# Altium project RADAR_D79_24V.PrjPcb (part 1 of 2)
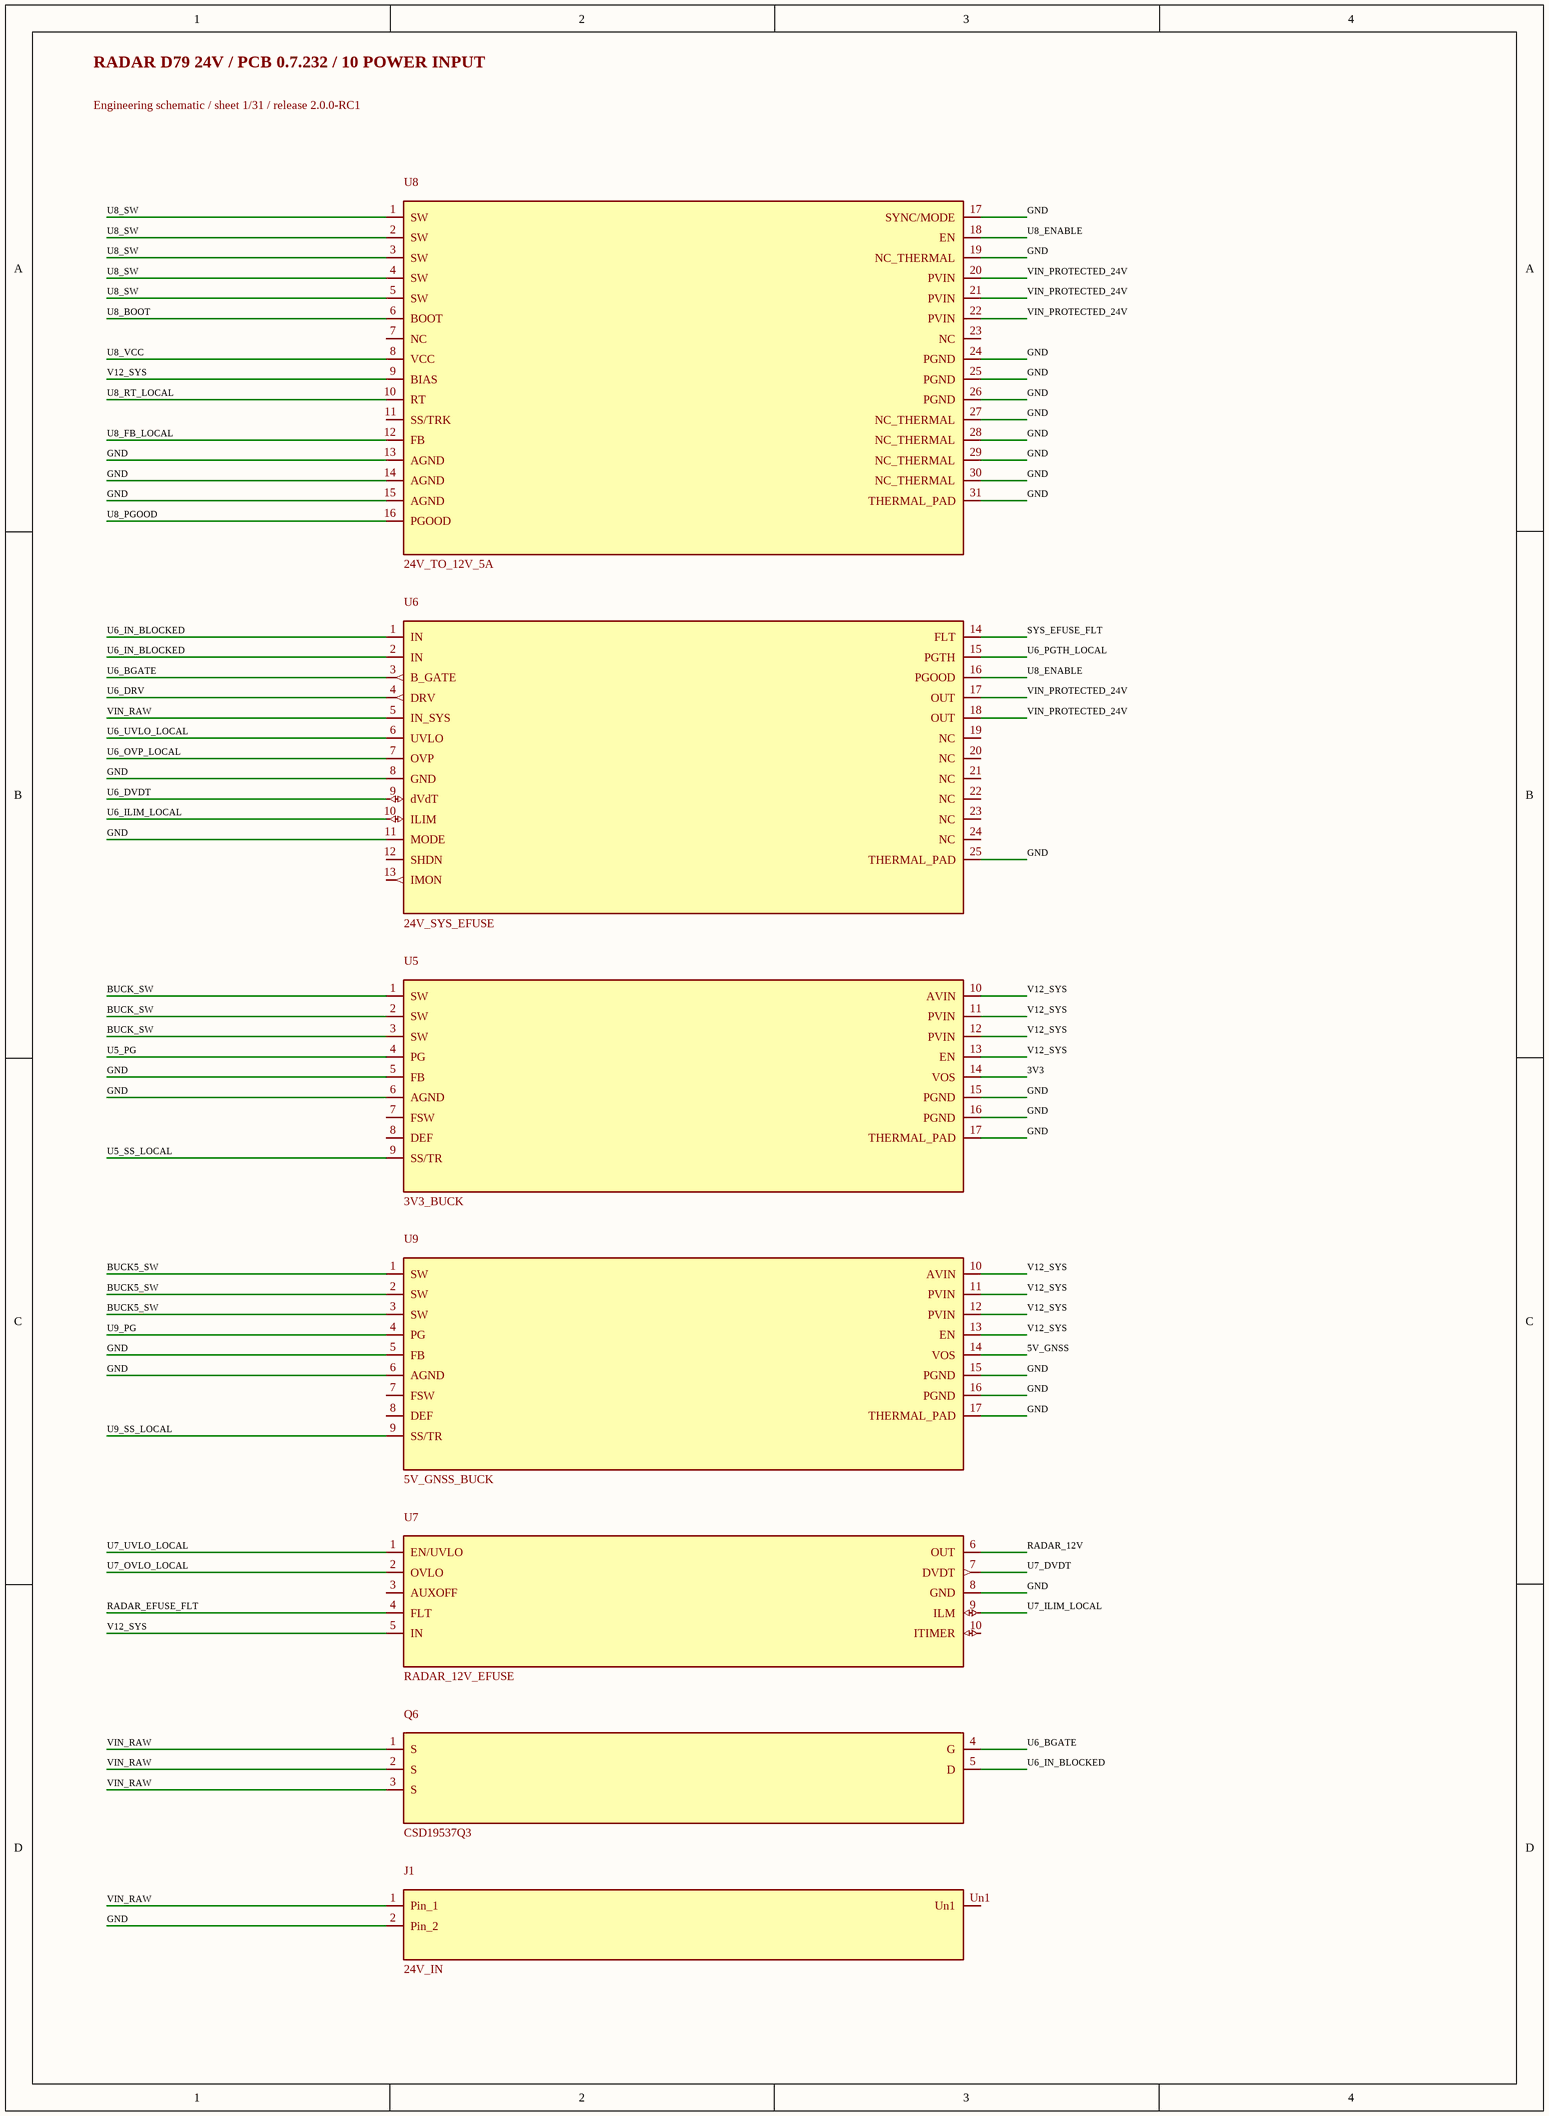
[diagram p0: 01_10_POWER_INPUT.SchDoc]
31 sheets, 304 parts. Net scope: global (net labels, ports and power ports of the same name join across sheets).
Board file: RADAR_D79_POWER_24V_v0.7.232.PcbDoc
Sheets:
  01_10_POWER_INPUT.SchDoc
  02_10_POWER_INPUT.SchDoc
  03_10_POWER_INPUT.SchDoc
  04_10_POWER_INPUT.SchDoc
  05_60_HOST_UART.SchDoc
  06_50_RADAR_IO_CAN.SchDoc
  07_70_DEBUG_BOOT.SchDoc
  08_30_TIME_GNSS.SchDoc
  09_20_MCU_CORE.SchDoc
  10_20_MCU_CORE.SchDoc
  11_20_MCU_CORE.SchDoc
  12_40_IMU.SchDoc
  13_Radar_interfaces_and_QSPI.SchDoc
  14_Radar_interfaces_and_QSPI.SchDoc
  15_Radar_interfaces_and_QSPI.SchDoc
  16_Radar_service_USB_and_boot.SchDoc
  17_Radar_service_USB_and_boot.SchDoc
  18_Radar_service_USB_and_boot.SchDoc
  19_Radar_12V_to_3V3.SchDoc
  20_Radar_12V_to_3V3.SchDoc
  21_Radar_input_and_reference.SchDoc
  22_Radar_bypass.SchDoc
  23_Radar_bypass.SchDoc
  24_Radar_bypass.SchDoc
  25_Radar_PMIC_and_rail_filters.SchDoc
  26_Radar_PMIC_and_rail_filters.SchDoc
  27_Radar_PMIC_and_rail_filters.SchDoc
  28_Radar_PMIC_and_rail_filters.SchDoc
  29_Radar_rail_selection_and_sensing.SchDoc
  30_Radar_rail_selection_and_sensing.SchDoc
  31_Radar_VPP_service.SchDoc

## Sheet 01_10_POWER_INPUT.SchDoc
size 289 x 396 mm

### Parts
J1  24V_IN  [Molex_43650-0200_RA_THT_2P]
Q6  CSD19537Q3  [VSON-8_3.3x3.3mm_P0.65mm_NexFET]
U5  3V3_BUCK  [VQFN-16-1EP_3x3mm_P0.5mm_EP1.68x1.68mm]
U6  24V_SYS_EFUSE  [Texas_RGE0024C_VQFN-24-1EP_4x4mm_P0.5mm_EP2.1x2.1mm]
U7  RADAR_12V_EFUSE  [TPS259470A_RPW0010A_VQFN-HR-10_2x2mm_P0.475mm]
U8  24V_TO_12V_5A  [Texas_RNP0030B_WQFN-30-1EP_4x6mm_P0.5mm_EP1.8x4.5mm_ThermalVias]
U9  5V_GNSS_BUCK  [VQFN-16-1EP_3x3mm_P0.5mm_EP1.68x1.68mm]

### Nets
3V3: U5.14(VOS)
5V_GNSS: U9.14(VOS)
BUCK5_SW: U9.1(SW) U9.2(SW) U9.3(SW)
BUCK_SW: U5.1(SW) U5.2(SW) U5.3(SW)
GND: J1.2(Pin_2) U5.5(FB) U5.6(AGND) U5.15(PGND) U5.16(PGND) U5.17(THERMAL_PAD) U6.8(GND) U6.11(MODE) U6.25(THERMAL_PAD) U7.8(GND) U8.13(AGND) U8.14(AGND) U8.15(AGND) U8.17(SYNC/MODE) U8.19(NC_THERMAL) U8.24(PGND) U8.25(PGND) U8.26(PGND) U8.27(NC_THERMAL) U8.28(NC_THERMAL) U8.29(NC_THERMAL) U8.30(NC_THERMAL) U8.31(THERMAL_PAD) U9.5(FB) U9.6(AGND) U9.15(PGND) U9.16(PGND) U9.17(THERMAL_PAD)
RADAR_12V: U7.6(OUT)
RADAR_EFUSE_FLT: U7.4(FLT)
SYS_EFUSE_FLT: U6.14(FLT)
U5_PG: U5.4(PG)
U5_SS_LOCAL: U5.9(SS/TR)
U6_BGATE: Q6.4(G) U6.3(B_GATE)
U6_DRV: U6.4(DRV)
U6_DVDT: U6.9(dVdT)
U6_ILIM_LOCAL: U6.10(ILIM)
U6_IN_BLOCKED: Q6.5(D) U6.1(IN) U6.2(IN)
U6_OVP_LOCAL: U6.7(OVP)
U6_PGTH_LOCAL: U6.15(PGTH)
U6_UVLO_LOCAL: U6.6(UVLO)
U7_DVDT: U7.7(DVDT)
U7_ILIM_LOCAL: U7.9(ILM)
U7_OVLO_LOCAL: U7.2(OVLO)
U7_UVLO_LOCAL: U7.1(EN/UVLO)
U8_BOOT: U8.6(BOOT)
U8_ENABLE: U6.16(PGOOD) U8.18(EN)
U8_FB_LOCAL: U8.12(FB)
U8_PGOOD: U8.16(PGOOD)
U8_RT_LOCAL: U8.10(RT)
U8_SW: U8.1(SW) U8.2(SW) U8.3(SW) U8.4(SW) U8.5(SW)
U8_VCC: U8.8(VCC)
U9_PG: U9.4(PG)
U9_SS_LOCAL: U9.9(SS/TR)
V12_SYS: U5.10(AVIN) U5.11(PVIN) U5.12(PVIN) U5.13(EN) U7.5(IN) U8.9(BIAS) U9.10(AVIN) U9.11(PVIN) U9.12(PVIN) U9.13(EN)
VIN_PROTECTED_24V: U6.17(OUT) U6.18(OUT) U8.20(PVIN) U8.21(PVIN) U8.22(PVIN)
VIN_RAW: J1.1(Pin_1) Q6.1(S) Q6.2(S) Q6.3(S) U6.5(IN_SYS)

Not connected (* = marked no-connect by the designer): J1 Un1; U5 7(FSW) 8(DEF); U6 12(SHDN) 13(IMON) 19(NC) 20(NC) 21(NC) 22(NC) 23(NC) 24(NC); U7 3(AUXOFF) 10(ITIMER); U8 7(NC) 11(SS/TRK) 23(NC); U9 7(FSW) 8(DEF)

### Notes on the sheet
- RADAR D79 24V / PCB 0.7.232 / 10 POWER INPUT
- Engineering schematic / sheet 1/31 / release 2.0.0-RC1

## Sheet 02_10_POWER_INPUT.SchDoc
size 289 x 396 mm
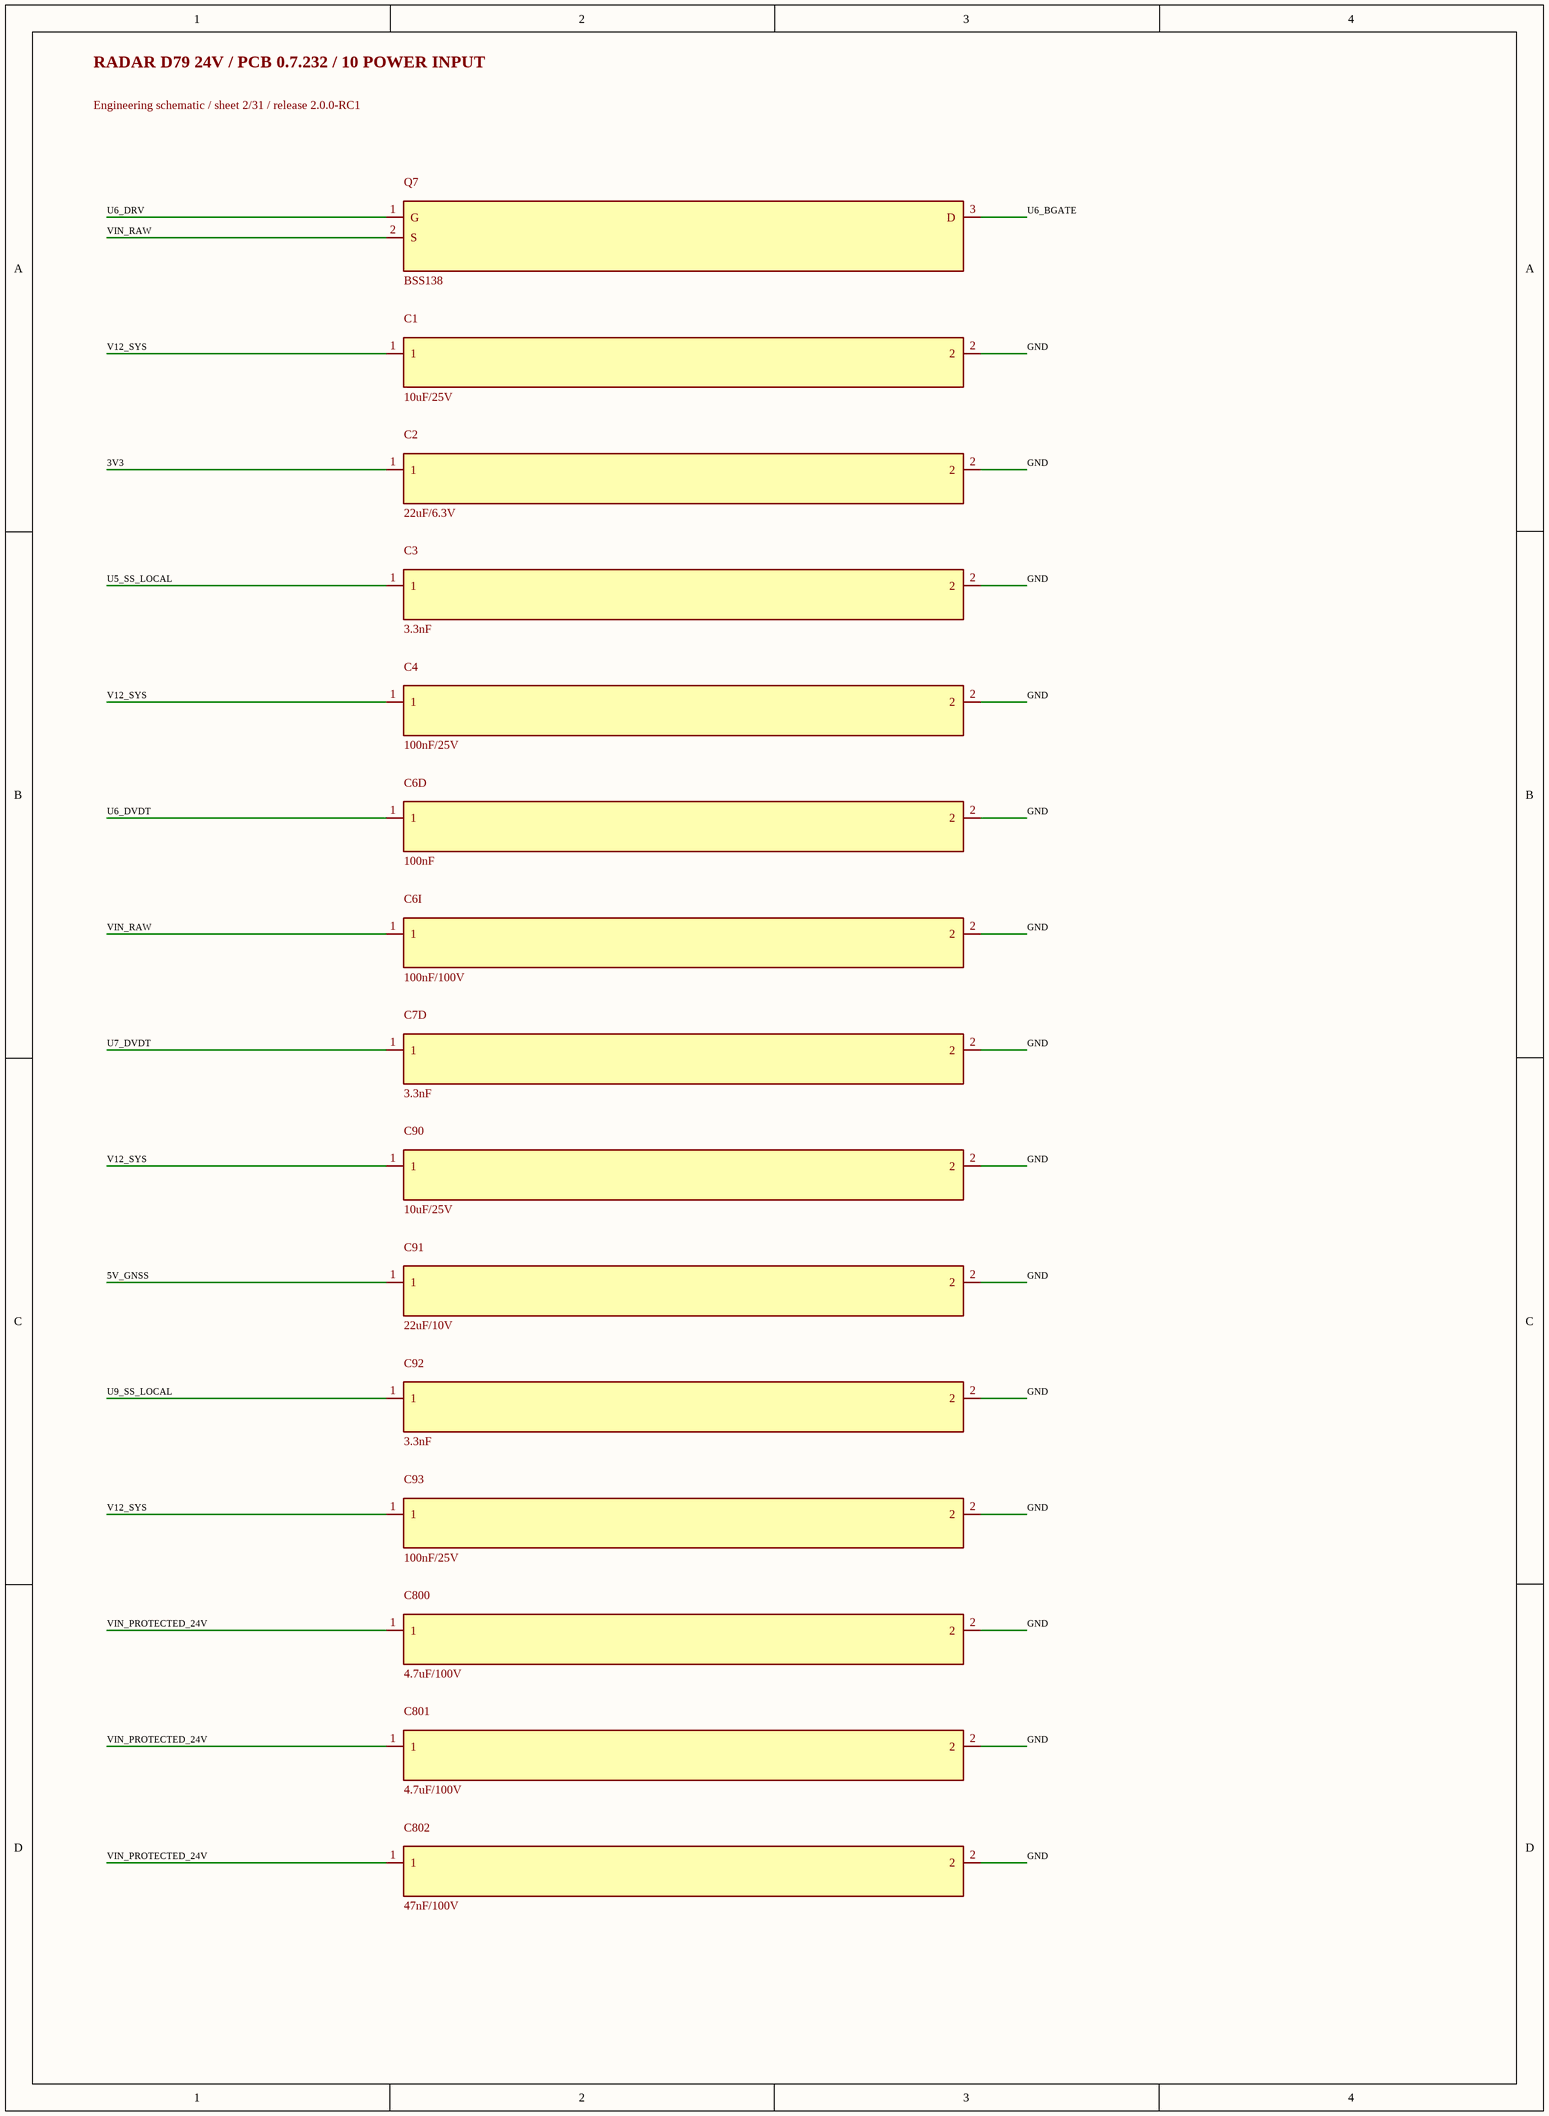
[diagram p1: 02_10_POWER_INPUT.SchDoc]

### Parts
C1  10uF/25V  [C_1206_3216Metric]
C2  22uF/6.3V  [C_1206_3216Metric]
C3  3.3nF  [C_0603_1608Metric]
C4  100nF/25V  [C_0603_1608Metric]
C6D  100nF  [C_0603_1608Metric]
C6I  100nF/100V  [C_0603_1608Metric]
C7D  3.3nF  [C_0603_1608Metric]
C90  10uF/25V  [C_1206_3216Metric]
C91  22uF/10V  [C_1206_3216Metric]
C92  3.3nF  [C_0603_1608Metric]
C93  100nF/25V  [C_0603_1608Metric]
C800  4.7uF/100V  [C_1210_3225Metric]
C801  4.7uF/100V  [C_1210_3225Metric]
C802  47nF/100V  [C_0603_1608Metric]
Q7  BSS138  [SOT-23]

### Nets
3V3: C2.1
5V_GNSS: C91.1
GND: C1.2 C2.2 C3.2 C4.2 C6D.2 C6I.2 C7D.2 C90.2 C91.2 C92.2 C93.2 C800.2 C801.2 C802.2
U5_SS_LOCAL: C3.1
U6_BGATE: Q7.3(D)
U6_DRV: Q7.1(G)
U6_DVDT: C6D.1
U7_DVDT: C7D.1
U9_SS_LOCAL: C92.1
V12_SYS: C1.1 C4.1 C90.1 C93.1
VIN_PROTECTED_24V: C800.1 C801.1 C802.1
VIN_RAW: C6I.1 Q7.2(S)

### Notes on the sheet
- RADAR D79 24V / PCB 0.7.232 / 10 POWER INPUT
- Engineering schematic / sheet 2/31 / release 2.0.0-RC1

## Sheet 03_10_POWER_INPUT.SchDoc
size 289 x 400 mm
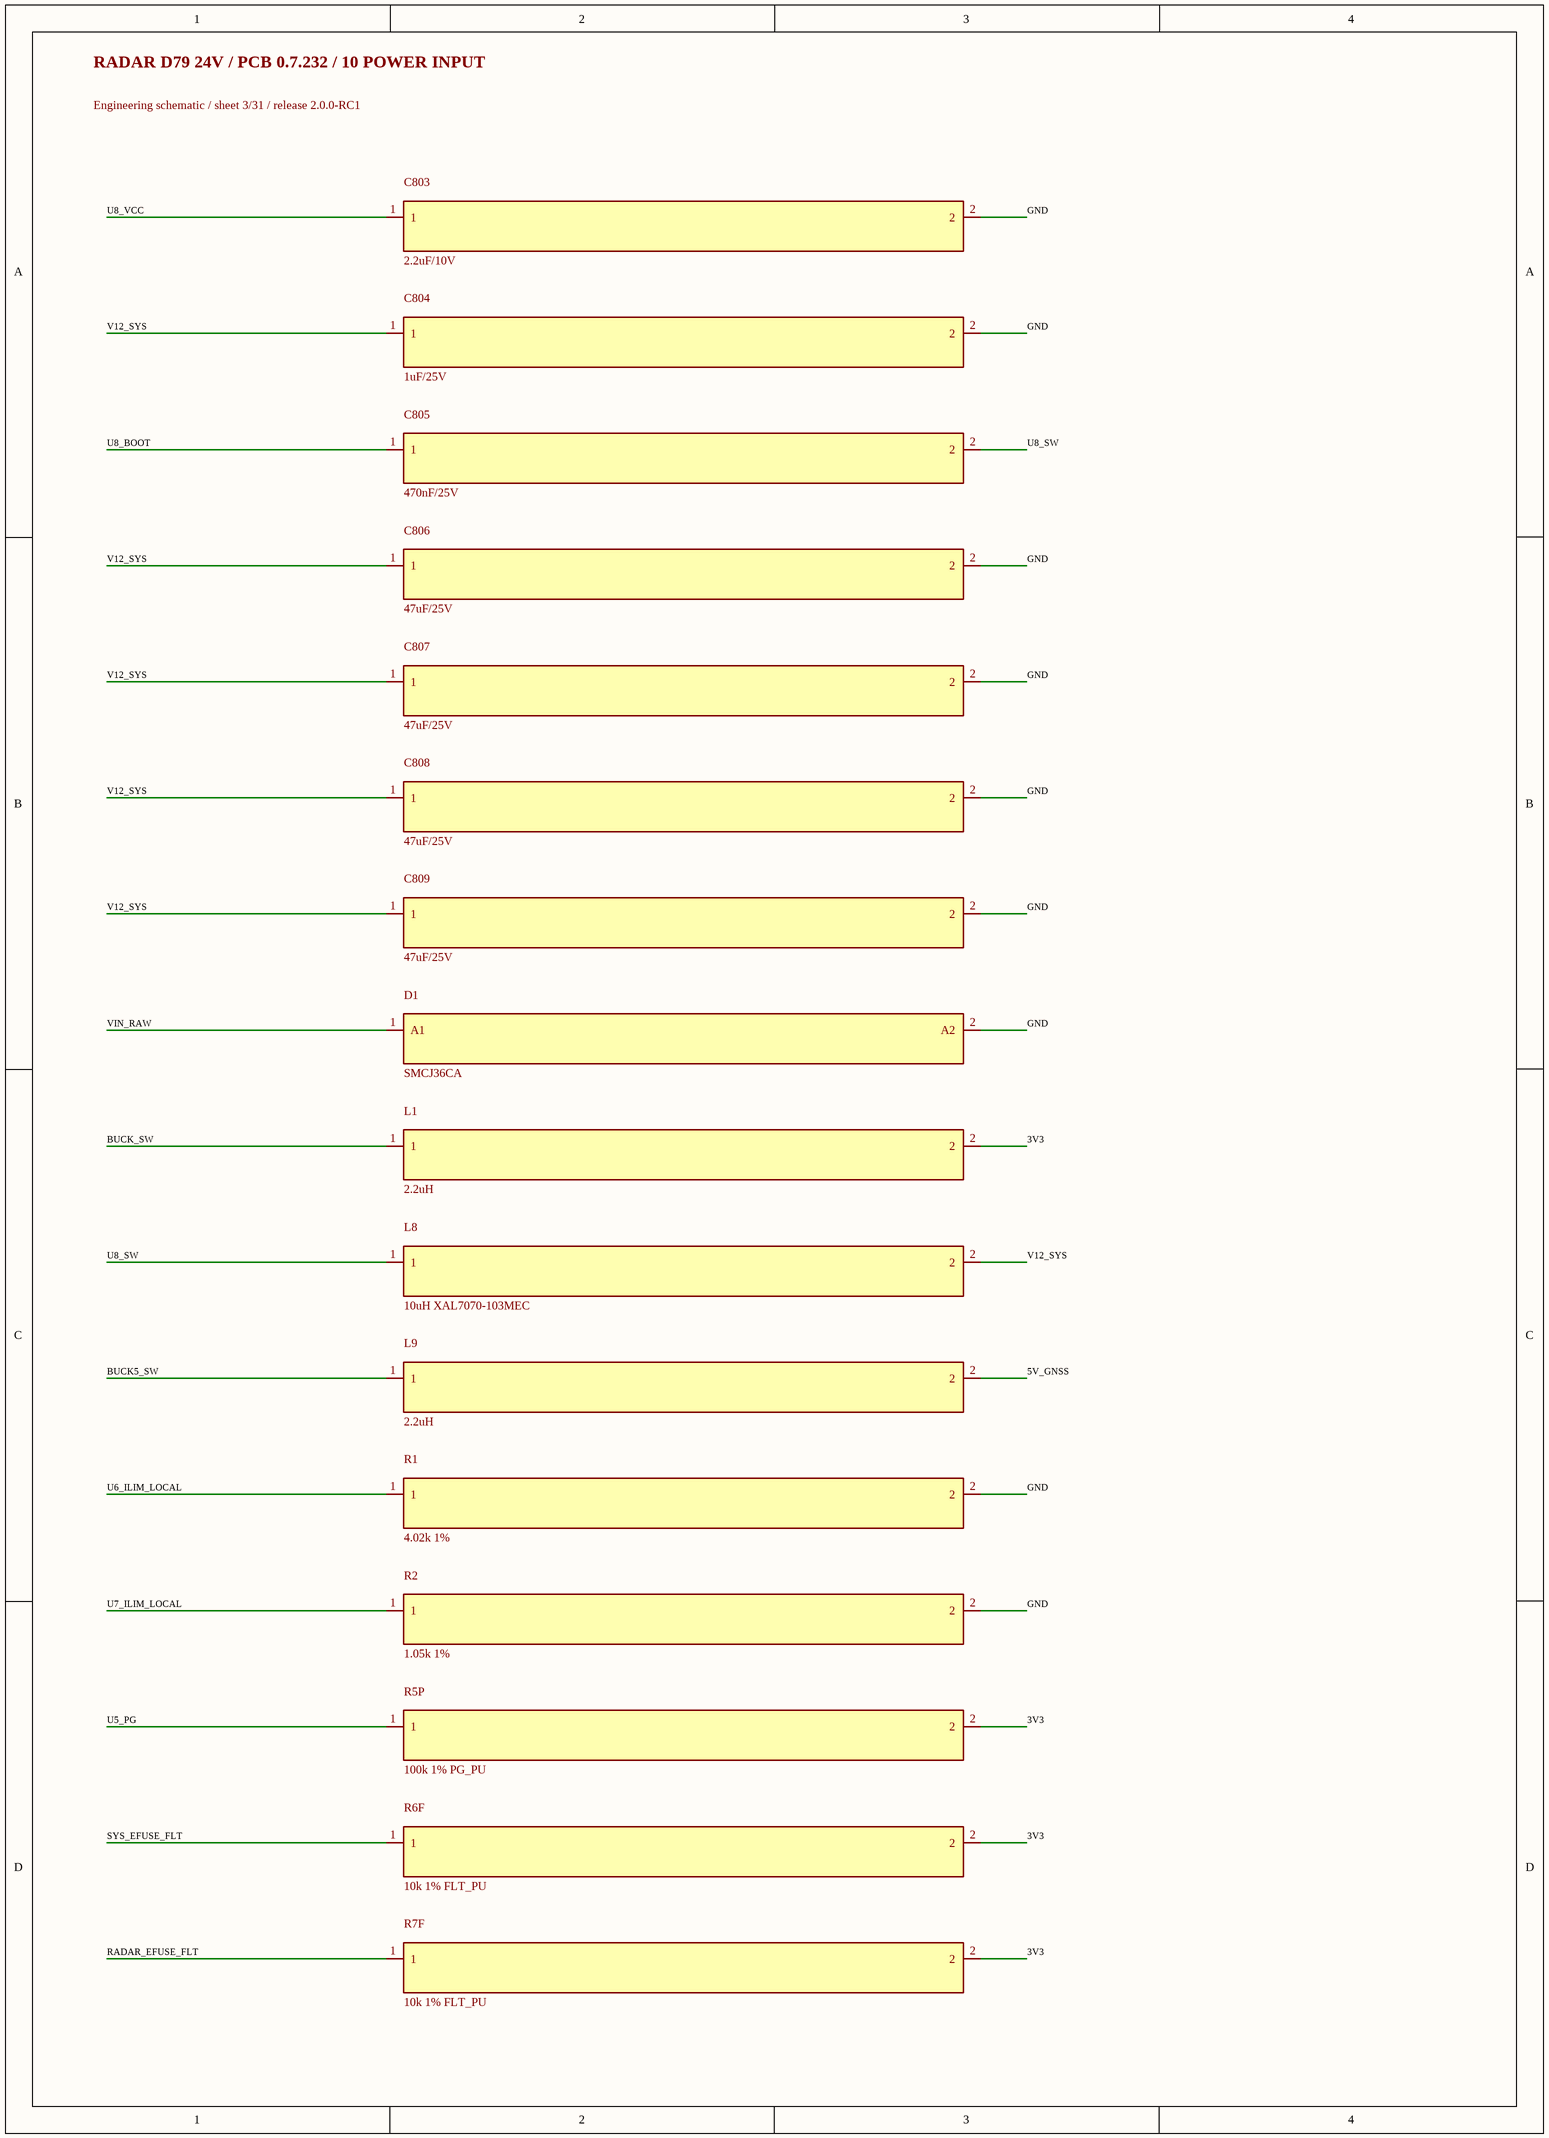
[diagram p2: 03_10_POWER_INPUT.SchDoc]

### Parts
C803  2.2uF/10V  [C_0603_1608Metric]
C804  1uF/25V  [C_0603_1608Metric]
C805  470nF/25V  [C_0603_1608Metric]
C806  47uF/25V  [C_1210_3225Metric]
C807  47uF/25V  [C_1210_3225Metric]
C808  47uF/25V  [C_1210_3225Metric]
C809  47uF/25V  [C_1210_3225Metric]
D1  SMCJ36CA  [D_SMC]
L1  2.2uH  [Coilcraft_XFL4020_4x4]
L8  10uH XAL7070-103MEC  [L_Coilcraft_XAL7070-XXX]
L9  2.2uH  [Coilcraft_XFL4020_4x4]
R1  4.02k 1%  [R_0603_1608Metric]
R2  1.05k 1%  [R_0603_1608Metric]
R5P  100k 1% PG_PU  [R_0603_1608Metric]
R6F  10k 1% FLT_PU  [R_0603_1608Metric]
R7F  10k 1% FLT_PU  [R_0603_1608Metric]

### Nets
3V3: L1.2 R5P.2 R6F.2 R7F.2
5V_GNSS: L9.2
BUCK5_SW: L9.1
BUCK_SW: L1.1
GND: C803.2 C804.2 C806.2 C807.2 C808.2 C809.2 D1.2(A2) R1.2 R2.2
RADAR_EFUSE_FLT: R7F.1
SYS_EFUSE_FLT: R6F.1
U5_PG: R5P.1
U6_ILIM_LOCAL: R1.1
U7_ILIM_LOCAL: R2.1
U8_BOOT: C805.1
U8_SW: C805.2 L8.1
U8_VCC: C803.1
V12_SYS: C804.1 C806.1 C807.1 C808.1 C809.1 L8.2
VIN_RAW: D1.1(A1)

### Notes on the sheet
- RADAR D79 24V / PCB 0.7.232 / 10 POWER INPUT
- Engineering schematic / sheet 3/31 / release 2.0.0-RC1

## Sheet 04_10_POWER_INPUT.SchDoc
size 289 x 396 mm
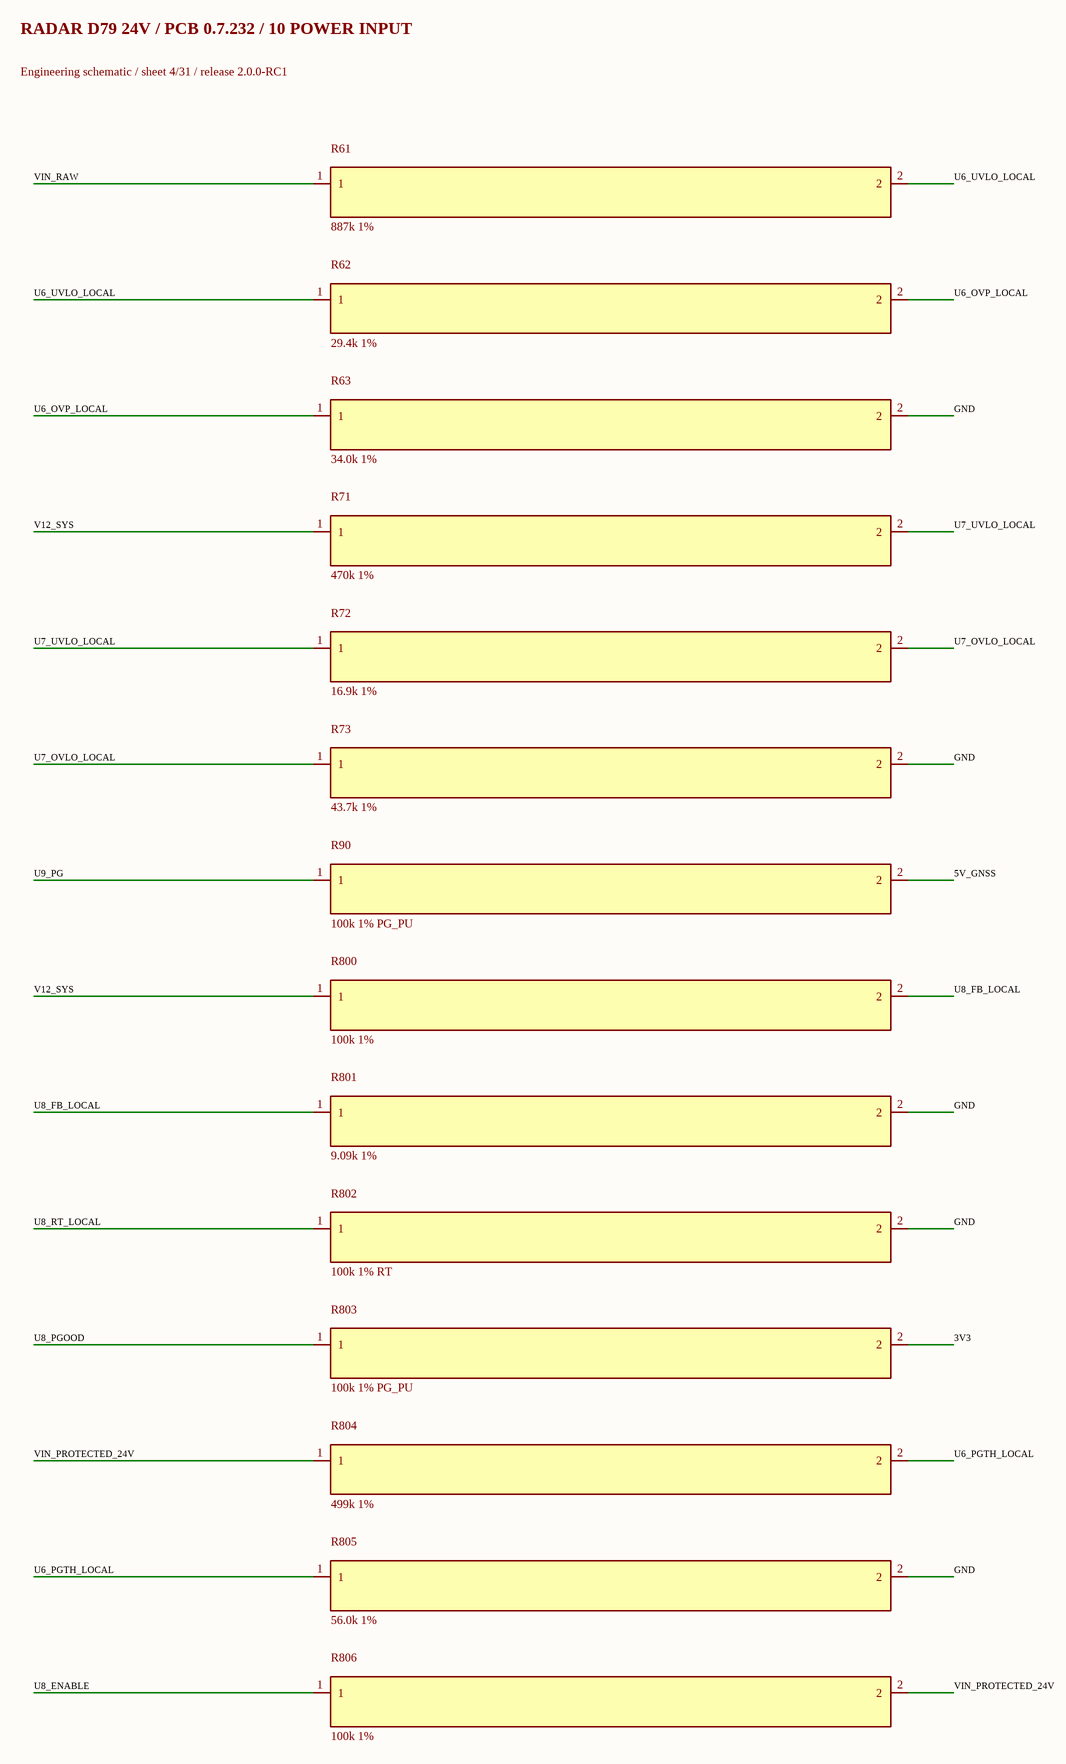
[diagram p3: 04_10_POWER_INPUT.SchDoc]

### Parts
R61  887k 1%  [R_0603_1608Metric]
R62  29.4k 1%  [R_0603_1608Metric]
R63  34.0k 1%  [R_0603_1608Metric]
R71  470k 1%  [R_0603_1608Metric]
R72  16.9k 1%  [R_0603_1608Metric]
R73  43.7k 1%  [R_0603_1608Metric]
R90  100k 1% PG_PU  [R_0603_1608Metric]
R800  100k 1%  [R_0603_1608Metric]
R801  9.09k 1%  [R_0603_1608Metric]
R802  100k 1% RT  [R_0603_1608Metric]
R803  100k 1% PG_PU  [R_0603_1608Metric]
R804  499k 1%  [R_0603_1608Metric]
R805  56.0k 1%  [R_0603_1608Metric]
R806  100k 1%  [R_0603_1608Metric]

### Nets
3V3: R803.2
5V_GNSS: R90.2
GND: R63.2 R73.2 R801.2 R802.2 R805.2
U6_OVP_LOCAL: R62.2 R63.1
U6_PGTH_LOCAL: R804.2 R805.1
U6_UVLO_LOCAL: R61.2 R62.1
U7_OVLO_LOCAL: R72.2 R73.1
U7_UVLO_LOCAL: R71.2 R72.1
U8_ENABLE: R806.1
U8_FB_LOCAL: R800.2 R801.1
U8_PGOOD: R803.1
U8_RT_LOCAL: R802.1
U9_PG: R90.1
V12_SYS: R71.1 R800.1
VIN_PROTECTED_24V: R804.1 R806.2
VIN_RAW: R61.1

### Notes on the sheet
- RADAR D79 24V / PCB 0.7.232 / 10 POWER INPUT
- Engineering schematic / sheet 4/31 / release 2.0.0-RC1

## Sheet 05_60_HOST_UART.SchDoc
size 289 x 396 mm
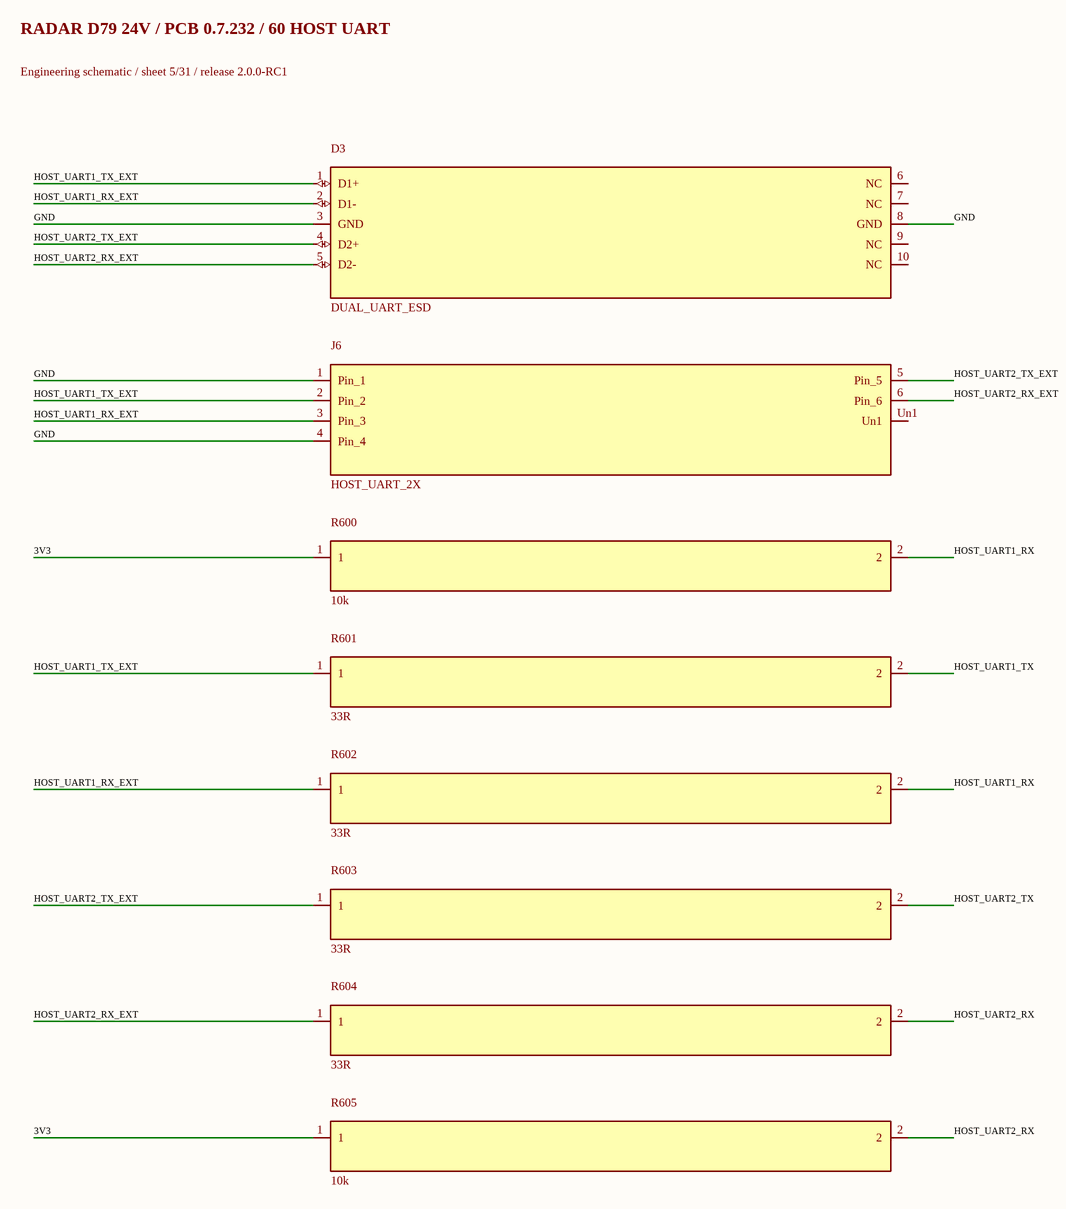
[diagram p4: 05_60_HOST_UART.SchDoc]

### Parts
D3  DUAL_UART_ESD  [USON-10_2.5x1.0mm_P0.5mm]
J6  HOST_UART_2X  [Molex_43045-0600_RA_THT_6P]
R600  10k  [R_0603_1608Metric]
R601  33R  [R_0402_1005Metric]
R602  33R  [R_0402_1005Metric]
R603  33R  [R_0402_1005Metric]
R604  33R  [R_0402_1005Metric]
R605  10k  [R_0603_1608Metric]

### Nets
3V3: R600.1 R605.1
GND: D3.3(GND) D3.8(GND) J6.1(Pin_1) J6.4(Pin_4)
HOST_UART1_RX: R600.2 R602.2
HOST_UART1_RX_EXT: D3.2(D1-) J6.3(Pin_3) R602.1
HOST_UART1_TX: R601.2
HOST_UART1_TX_EXT: D3.1(D1+) J6.2(Pin_2) R601.1
HOST_UART2_RX: R604.2 R605.2
HOST_UART2_RX_EXT: D3.5(D2-) J6.6(Pin_6) R604.1
HOST_UART2_TX: R603.2
HOST_UART2_TX_EXT: D3.4(D2+) J6.5(Pin_5) R603.1

Not connected (* = marked no-connect by the designer): D3 6(NC) 7(NC) 9(NC) 10(NC); J6 Un1

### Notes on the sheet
- RADAR D79 24V / PCB 0.7.232 / 60 HOST UART
- Engineering schematic / sheet 5/31 / release 2.0.0-RC1

## Sheet 06_50_RADAR_IO_CAN.SchDoc
size 289 x 396 mm
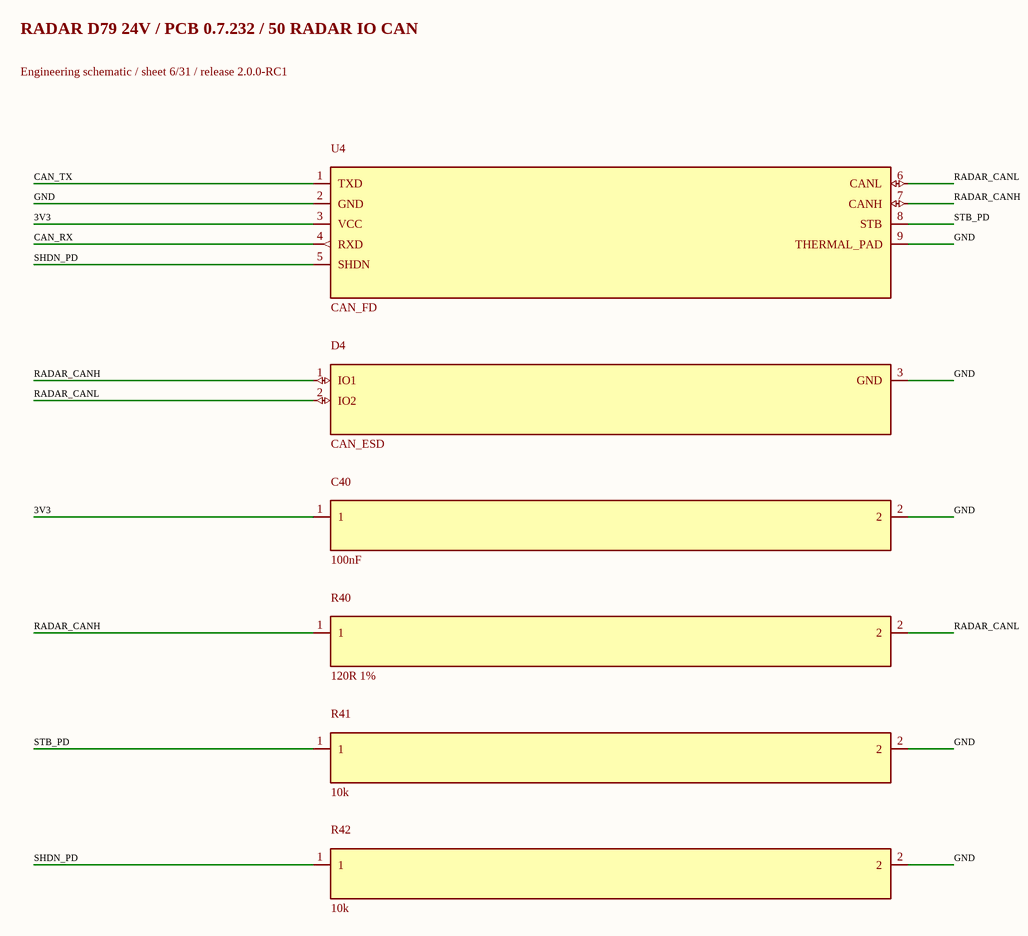
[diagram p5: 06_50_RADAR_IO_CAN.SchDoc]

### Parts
C40  100nF  [C_0402_1005Metric]
D4  CAN_ESD  [SOT-23]
R40  120R 1%  [R_0603_1608Metric]
R41  10k  [R_0603_1608Metric]
R42  10k  [R_0603_1608Metric]
U4  CAN_FD  [Texas_DRB0008A]

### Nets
3V3: C40.1 U4.3(VCC)
CAN_RX: U4.4(RXD)
CAN_TX: U4.1(TXD)
GND: C40.2 D4.3(GND) R41.2 R42.2 U4.2(GND) U4.9(THERMAL_PAD)
RADAR_CANH: D4.1(IO1) R40.1 U4.7(CANH)
RADAR_CANL: D4.2(IO2) R40.2 U4.6(CANL)
SHDN_PD: R42.1 U4.5(SHDN)
STB_PD: R41.1 U4.8(STB)

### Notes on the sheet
- RADAR D79 24V / PCB 0.7.232 / 50 RADAR IO CAN
- Engineering schematic / sheet 6/31 / release 2.0.0-RC1

## Sheet 07_70_DEBUG_BOOT.SchDoc
size 289 x 396 mm
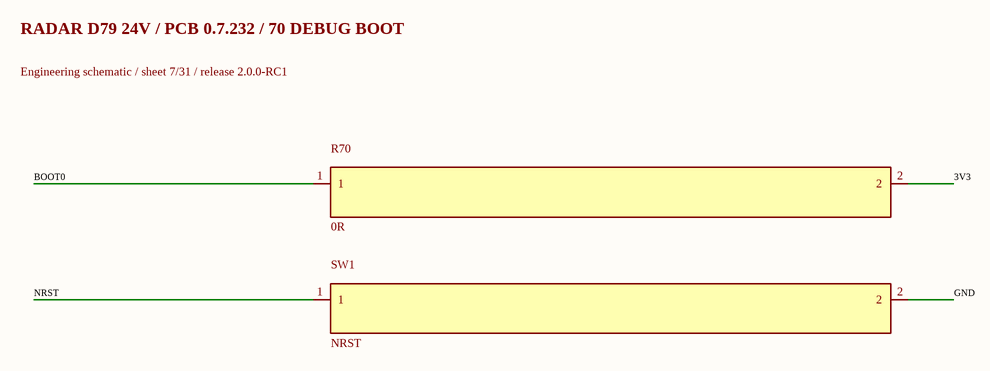
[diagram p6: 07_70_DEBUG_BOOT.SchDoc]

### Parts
R70  0R  [R_0603_1608Metric]
SW1  NRST  [ESwitch_TL3301_GullWing_6x6]

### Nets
3V3: R70.2
BOOT0: R70.1
GND: SW1.2
NRST: SW1.1

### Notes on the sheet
- RADAR D79 24V / PCB 0.7.232 / 70 DEBUG BOOT
- Engineering schematic / sheet 7/31 / release 2.0.0-RC1

## Sheet 08_30_TIME_GNSS.SchDoc
size 289 x 396 mm
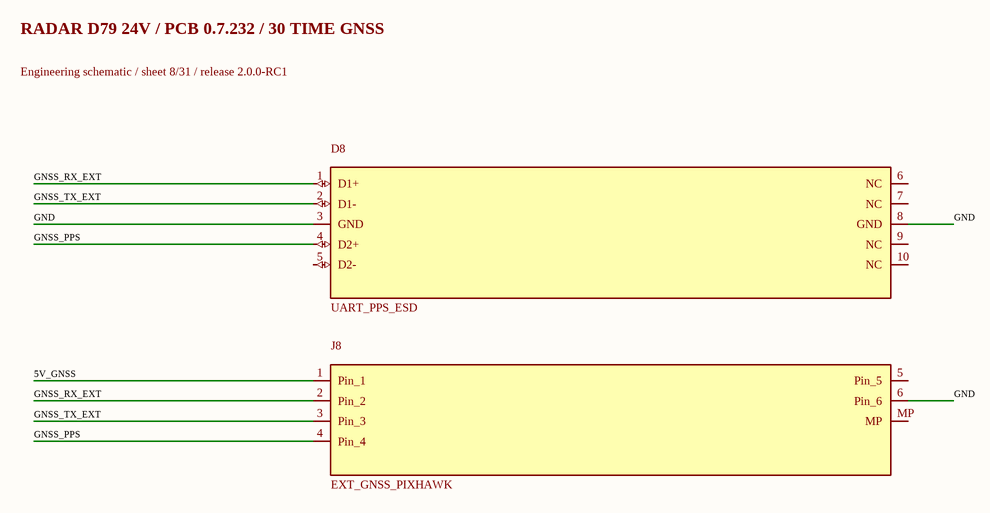
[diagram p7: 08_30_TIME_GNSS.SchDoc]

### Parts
D8  UART_PPS_ESD  [USON-10_2.5x1.0mm_P0.5mm]
J8  EXT_GNSS_PIXHAWK  [JST_GH_SM06B-GHS-TB_1x06-1MP_P1.25mm_Horizontal]

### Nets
5V_GNSS: J8.1(Pin_1)
GND: D8.3(GND) D8.8(GND) J8.6(Pin_6)
GNSS_PPS: D8.4(D2+) J8.4(Pin_4)
GNSS_RX_EXT: D8.1(D1+) J8.2(Pin_2)
GNSS_TX_EXT: D8.2(D1-) J8.3(Pin_3)

Not connected (* = marked no-connect by the designer): D8 5(D2-) 6(NC) 7(NC) 9(NC) 10(NC); J8 5(Pin_5) MP

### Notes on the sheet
- RADAR D79 24V / PCB 0.7.232 / 30 TIME GNSS
- Engineering schematic / sheet 8/31 / release 2.0.0-RC1

## Sheet 09_20_MCU_CORE.SchDoc
size 289 x 404 mm
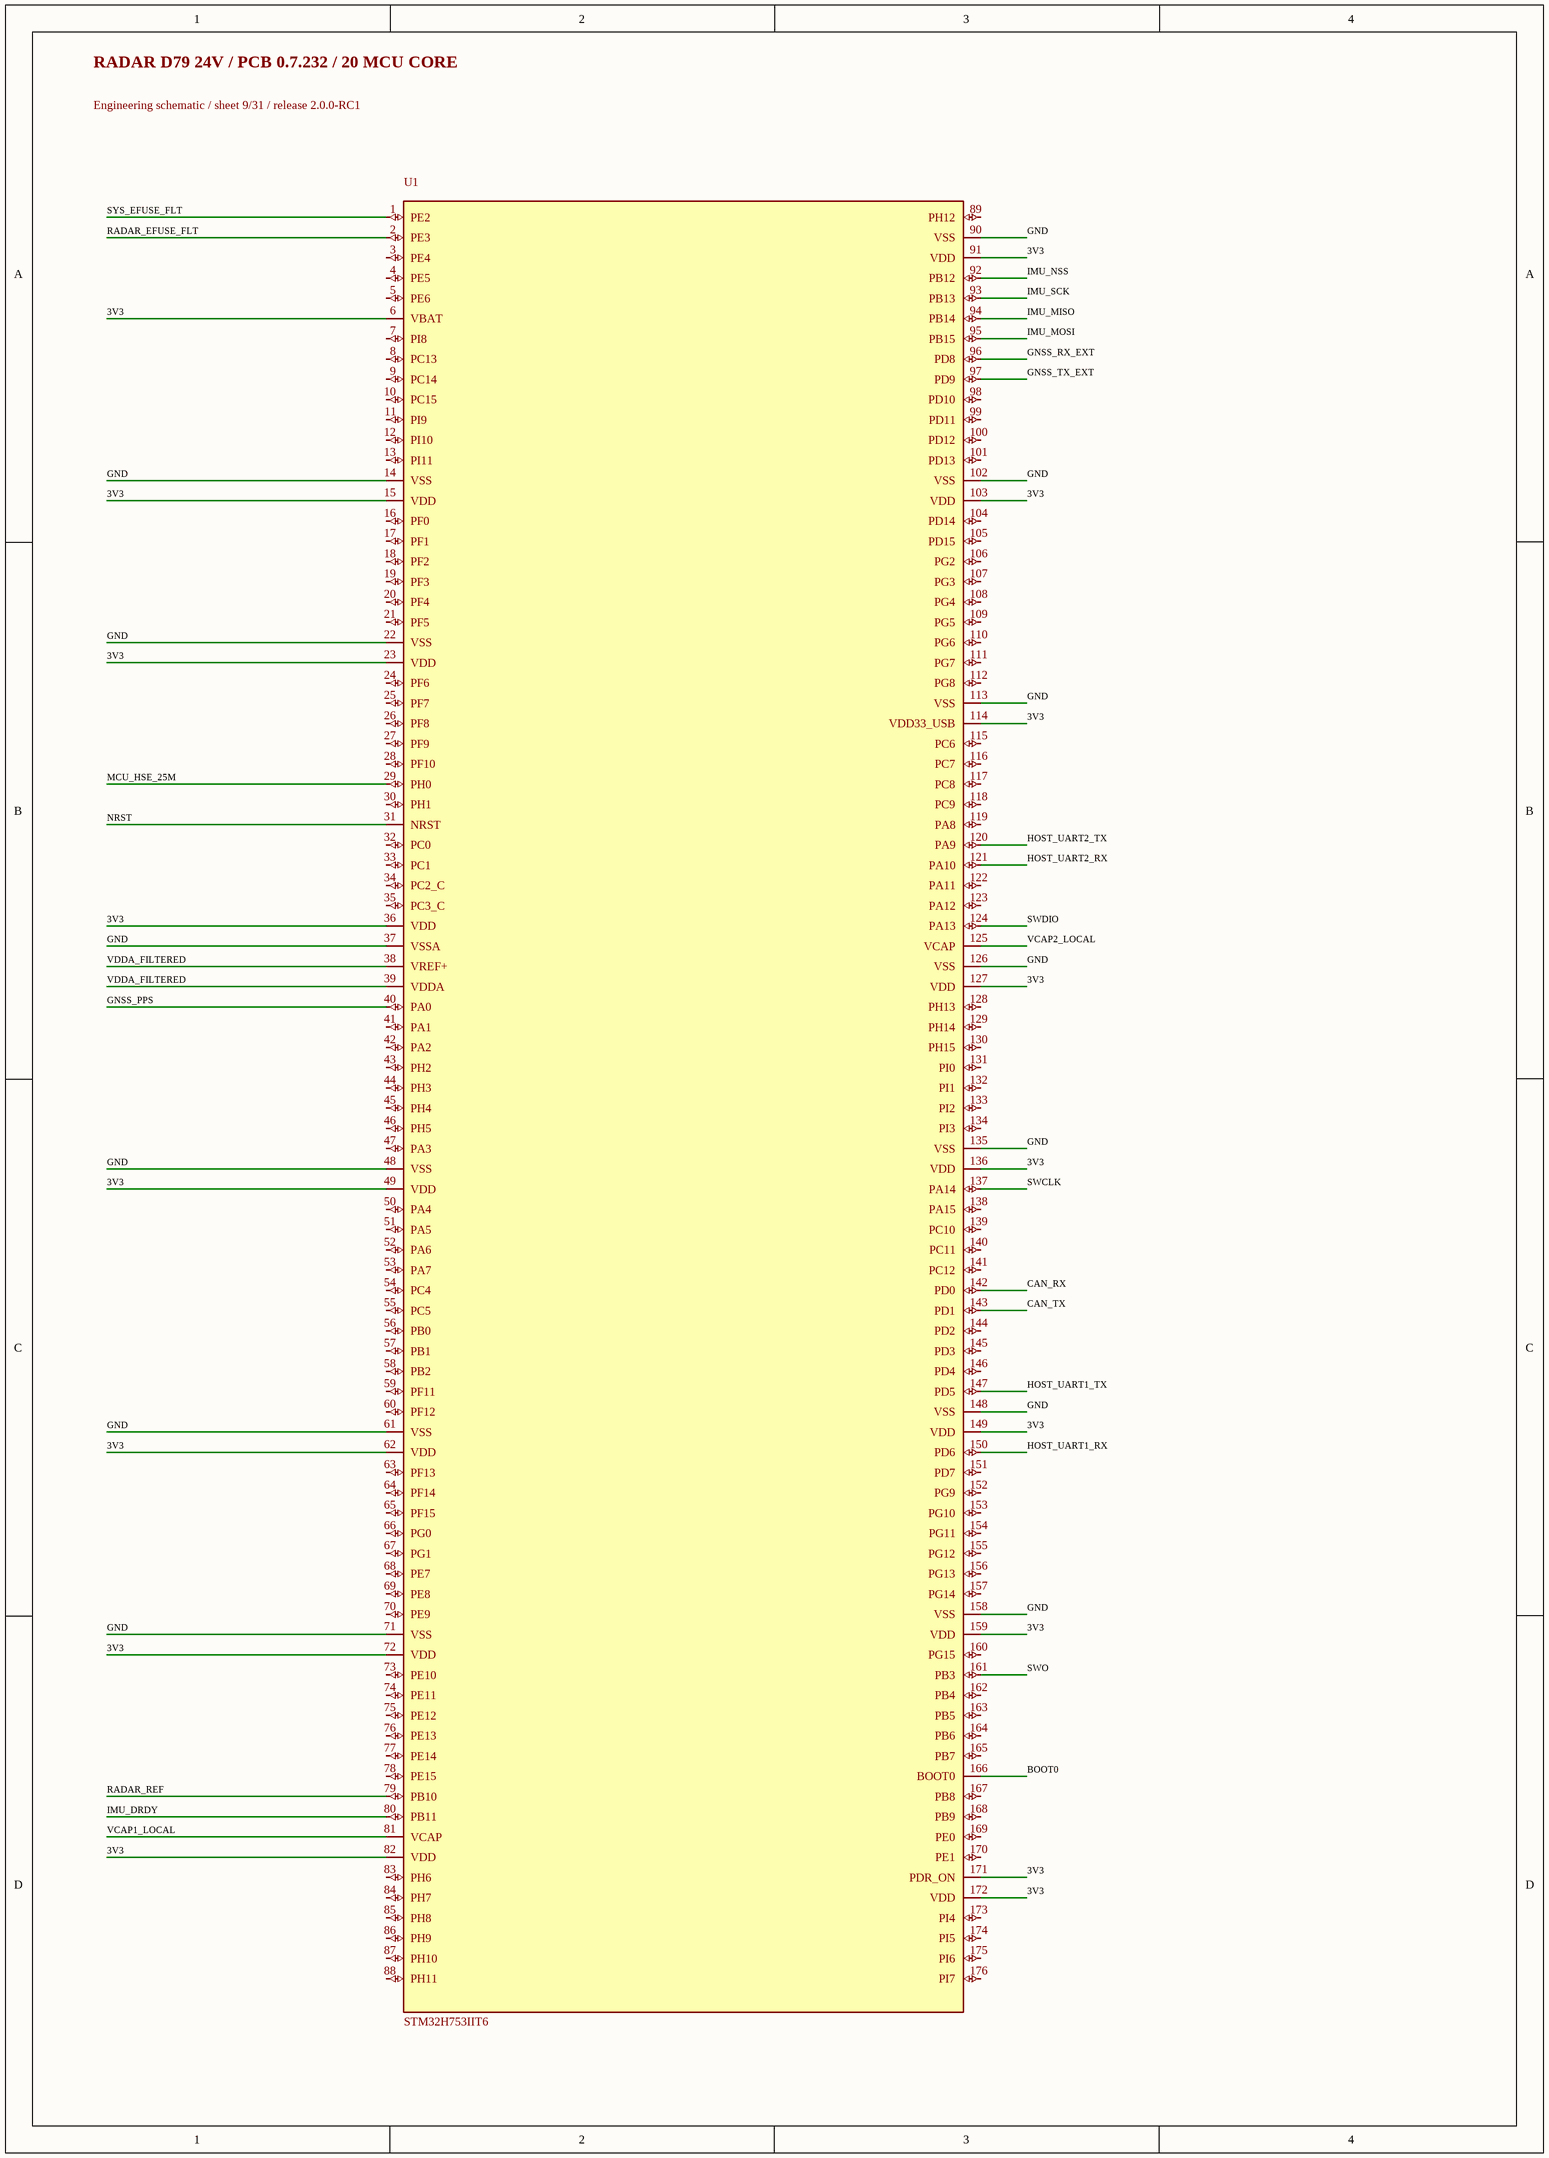
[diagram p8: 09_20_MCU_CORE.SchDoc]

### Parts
U1  STM32H753IIT6  [LQFP-176_24x24mm_P0.5mm]

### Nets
3V3: U1.6(VBAT) U1.15(VDD) U1.23(VDD) U1.36(VDD) U1.49(VDD) U1.62(VDD) U1.72(VDD) U1.82(VDD) U1.91(VDD) U1.103(VDD) U1.114(VDD33_USB) U1.127(VDD) U1.136(VDD) U1.149(VDD) U1.159(VDD) U1.171(PDR_ON) U1.172(VDD)
BOOT0: U1.166(BOOT0)
CAN_RX: U1.142(PD0)
CAN_TX: U1.143(PD1)
GND: U1.14(VSS) U1.22(VSS) U1.37(VSSA) U1.48(VSS) U1.61(VSS) U1.71(VSS) U1.90(VSS) U1.102(VSS) U1.113(VSS) U1.126(VSS) U1.135(VSS) U1.148(VSS) U1.158(VSS)
GNSS_PPS: U1.40(PA0)
GNSS_RX_EXT: U1.96(PD8)
GNSS_TX_EXT: U1.97(PD9)
HOST_UART1_RX: U1.150(PD6)
HOST_UART1_TX: U1.147(PD5)
HOST_UART2_RX: U1.121(PA10)
HOST_UART2_TX: U1.120(PA9)
IMU_DRDY: U1.80(PB11)
IMU_MISO: U1.94(PB14)
IMU_MOSI: U1.95(PB15)
IMU_NSS: U1.92(PB12)
IMU_SCK: U1.93(PB13)
MCU_HSE_25M: U1.29(PH0)
NRST: U1.31(NRST)
RADAR_EFUSE_FLT: U1.2(PE3)
RADAR_REF: U1.79(PB10)
SWCLK: U1.137(PA14)
SWDIO: U1.124(PA13)
SWO: U1.161(PB3)
SYS_EFUSE_FLT: U1.1(PE2)
VCAP1_LOCAL: U1.81(VCAP)
VCAP2_LOCAL: U1.125(VCAP)
VDDA_FILTERED: U1.38(VREF+) U1.39(VDDA)

Not connected (* = marked no-connect by the designer): U1 3(PE4) 4(PE5) 5(PE6) 7(PI8) 8(PC13) 9(PC14) 10(PC15) 11(PI9) 12(PI10) 13(PI11) 16(PF0) 17(PF1) 18(PF2) 19(PF3) 20(PF4) 21(PF5) 24(PF6) 25(PF7) 26(PF8) 27(PF9) 28(PF10) 30(PH1) 32(PC0) 33(PC1) 34(PC2_C) 35(PC3_C) 41(PA1) 42(PA2) 43(PH2) 44(PH3) 45(PH4) 46(PH5) 47(PA3) 50(PA4) 51(PA5) 52(PA6) 53(PA7) 54(PC4) 55(PC5) 56(PB0) 57(PB1) 58(PB2) 59(PF11) 60(PF12) 63(PF13) 64(PF14) 65(PF15) 66(PG0) 67(PG1) 68(PE7) 69(PE8) 70(PE9) 73(PE10) 74(PE11) 75(PE12) 76(PE13) 77(PE14) 78(PE15) 83(PH6) 84(PH7) 85(PH8) 86(PH9) 87(PH10) 88(PH11) 89(PH12) 98(PD10) 99(PD11) 100(PD12) 101(PD13) 104(PD14) 105(PD15) 106(PG2) 107(PG3) 108(PG4) 109(PG5) 110(PG6) 111(PG7) 112(PG8) 115(PC6) 116(PC7) 117(PC8) 118(PC9) 119(PA8) 122(PA11) 123(PA12) 128(PH13) 129(PH14) 130(PH15) 131(PI0) 132(PI1) 133(PI2) 134(PI3) 138(PA15) 139(PC10) 140(PC11) 141(PC12) 144(PD2) 145(PD3) 146(PD4) 151(PD7) 152(PG9) 153(PG10) 154(PG11) 155(PG12) 156(PG13) 157(PG14) 160(PG15) 162(PB4) 163(PB5) 164(PB6) 165(PB7) 167(PB8) 168(PB9) 169(PE0) 170(PE1) 173(PI4) 174(PI5) 175(PI6) 176(PI7)

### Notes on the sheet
- RADAR D79 24V / PCB 0.7.232 / 20 MCU CORE
- Engineering schematic / sheet 9/31 / release 2.0.0-RC1

## Sheet 10_20_MCU_CORE.SchDoc
size 289 x 397 mm
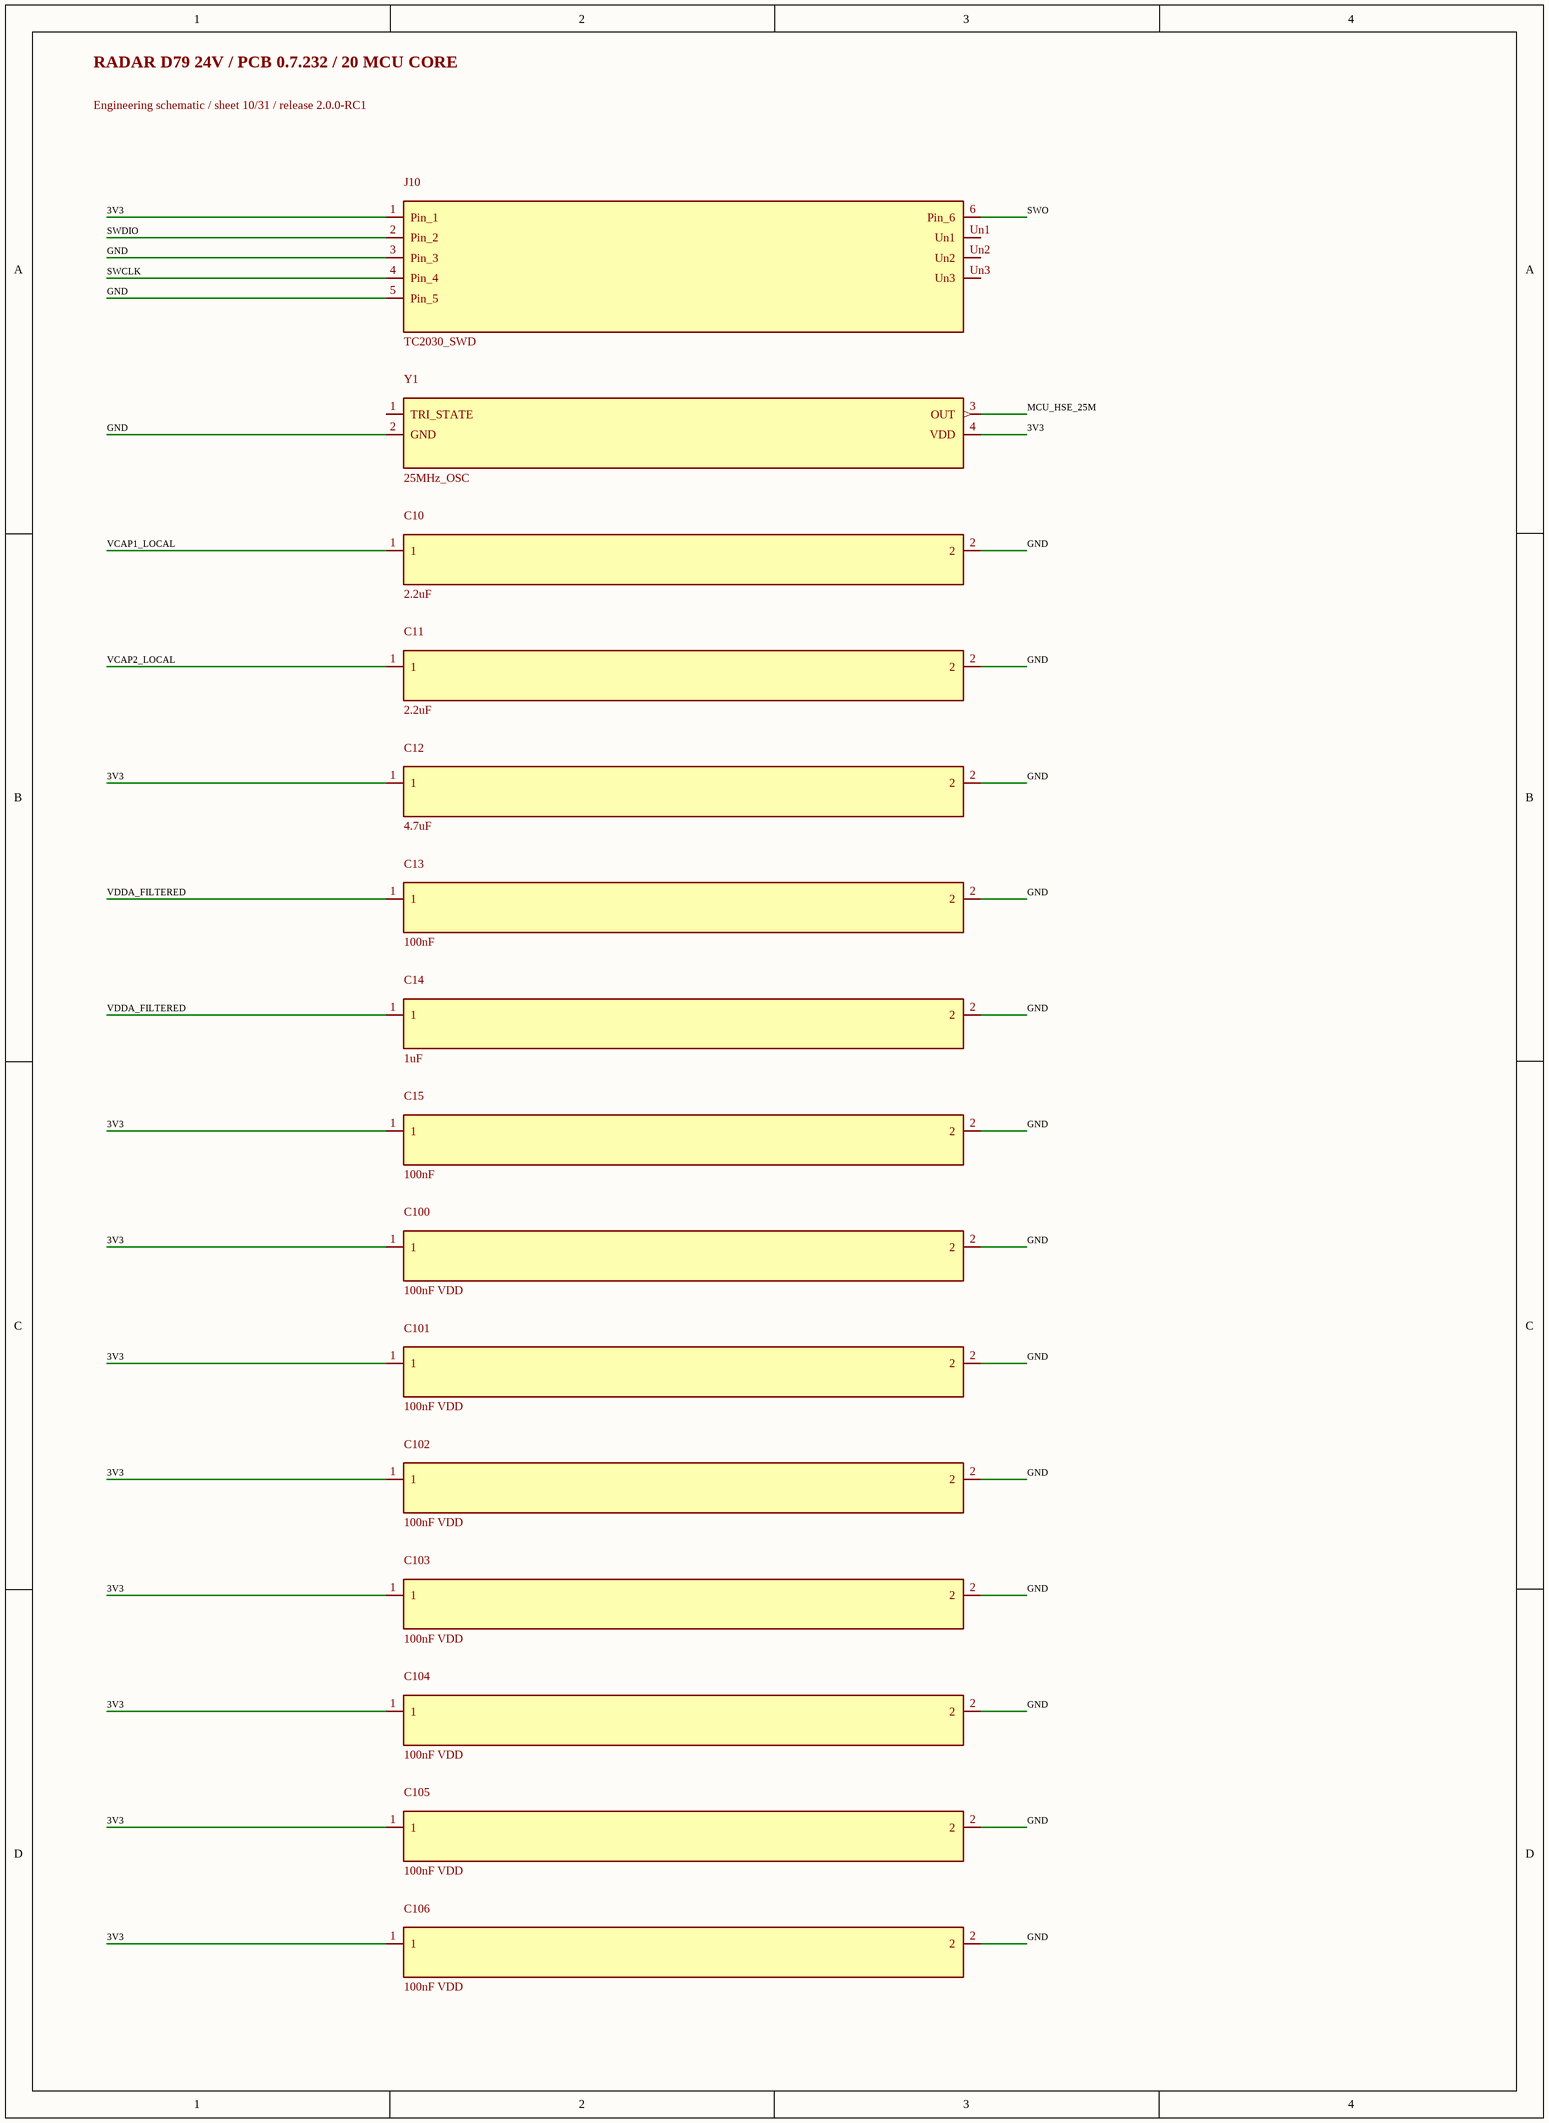
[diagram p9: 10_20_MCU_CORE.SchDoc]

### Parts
C10  2.2uF  [C_0603_1608Metric]
C11  2.2uF  [C_0603_1608Metric]
C12  4.7uF  [C_0805_2012Metric]
C13  100nF  [C_0402_1005Metric]
C14  1uF  [C_0603_1608Metric]
C15  100nF  [C_0402_1005Metric]
C100  100nF VDD  [C_0402_1005Metric]
C101  100nF VDD  [C_0402_1005Metric]
C102  100nF VDD  [C_0402_1005Metric]
C103  100nF VDD  [C_0402_1005Metric]
C104  100nF VDD  [C_0402_1005Metric]
C105  100nF VDD  [C_0402_1005Metric]
C106  100nF VDD  [C_0402_1005Metric]
J10  TC2030_SWD  [TagConnect_TC2030_NL]
Y1  25MHz_OSC  [Oscillator_SMD_ECS_2520MV-xxx-xx-4Pin_2.5x2.0mm]

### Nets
3V3: C12.1 C15.1 C100.1 C101.1 C102.1 C103.1 C104.1 C105.1 C106.1 J10.1(Pin_1) Y1.4(VDD)
GND: C10.2 C11.2 C12.2 C13.2 C14.2 C15.2 C100.2 C101.2 C102.2 C103.2 C104.2 C105.2 C106.2 J10.3(Pin_3) J10.5(Pin_5) Y1.2(GND)
MCU_HSE_25M: Y1.3(OUT)
SWCLK: J10.4(Pin_4)
SWDIO: J10.2(Pin_2)
SWO: J10.6(Pin_6)
VCAP1_LOCAL: C10.1
VCAP2_LOCAL: C11.1
VDDA_FILTERED: C13.1 C14.1

Not connected (* = marked no-connect by the designer): J10 Un1 Un2 Un3; Y1 1(TRI_STATE)

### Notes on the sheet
- RADAR D79 24V / PCB 0.7.232 / 20 MCU CORE
- Engineering schematic / sheet 10/31 / release 2.0.0-RC1

## Sheet 11_20_MCU_CORE.SchDoc
size 289 x 396 mm
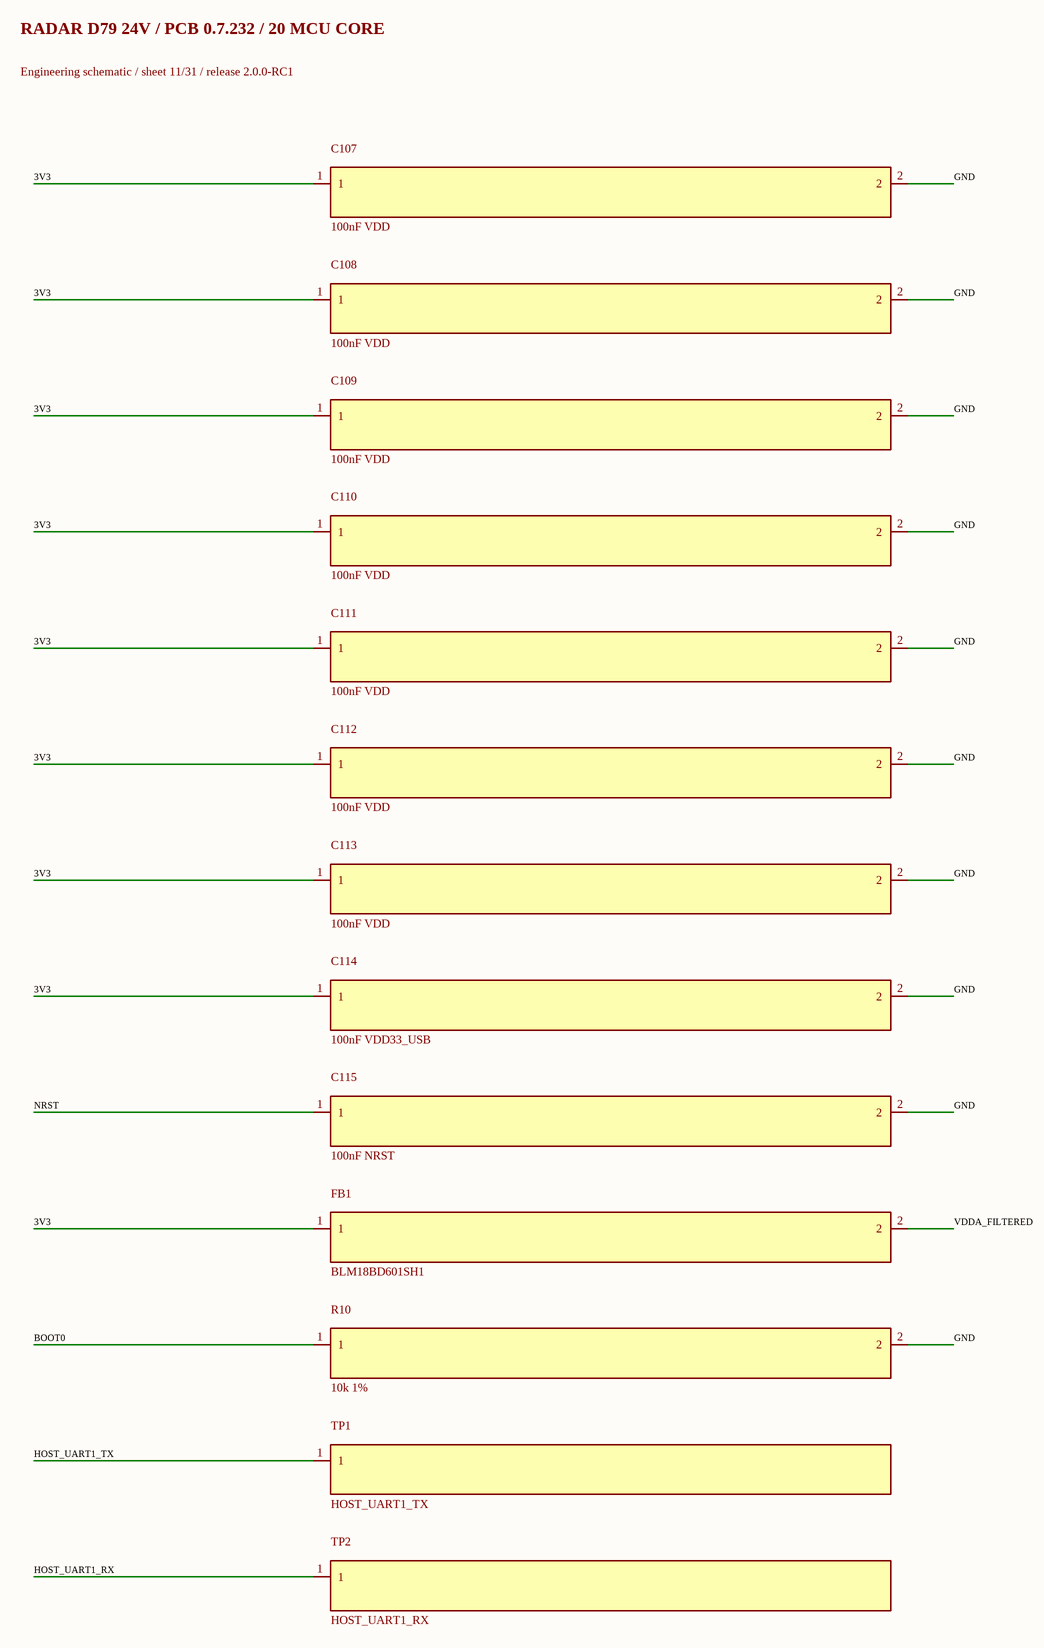
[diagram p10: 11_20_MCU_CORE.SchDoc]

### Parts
C107  100nF VDD  [C_0402_1005Metric]
C108  100nF VDD  [C_0402_1005Metric]
C109  100nF VDD  [C_0402_1005Metric]
C110  100nF VDD  [C_0402_1005Metric]
C111  100nF VDD  [C_0402_1005Metric]
C112  100nF VDD  [C_0402_1005Metric]
C113  100nF VDD  [C_0402_1005Metric]
C114  100nF VDD33_USB  [C_0402_1005Metric]
C115  100nF NRST  [C_0402_1005Metric]
FB1  BLM18BD601SH1  [L_0603_1608Metric]
R10  10k 1%  [R_0603_1608Metric]
TP1  HOST_UART1_TX  [TestPoint_Pad_D1.0mm]
TP2  HOST_UART1_RX  [TestPoint_Pad_D1.0mm]

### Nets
3V3: C107.1 C108.1 C109.1 C110.1 C111.1 C112.1 C113.1 C114.1 FB1.1
BOOT0: R10.1
GND: C107.2 C108.2 C109.2 C110.2 C111.2 C112.2 C113.2 C114.2 C115.2 R10.2
HOST_UART1_RX: TP2.1
HOST_UART1_TX: TP1.1
NRST: C115.1
VDDA_FILTERED: FB1.2

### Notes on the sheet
- RADAR D79 24V / PCB 0.7.232 / 20 MCU CORE
- Engineering schematic / sheet 11/31 / release 2.0.0-RC1

## Sheet 12_40_IMU.SchDoc
size 289 x 396 mm
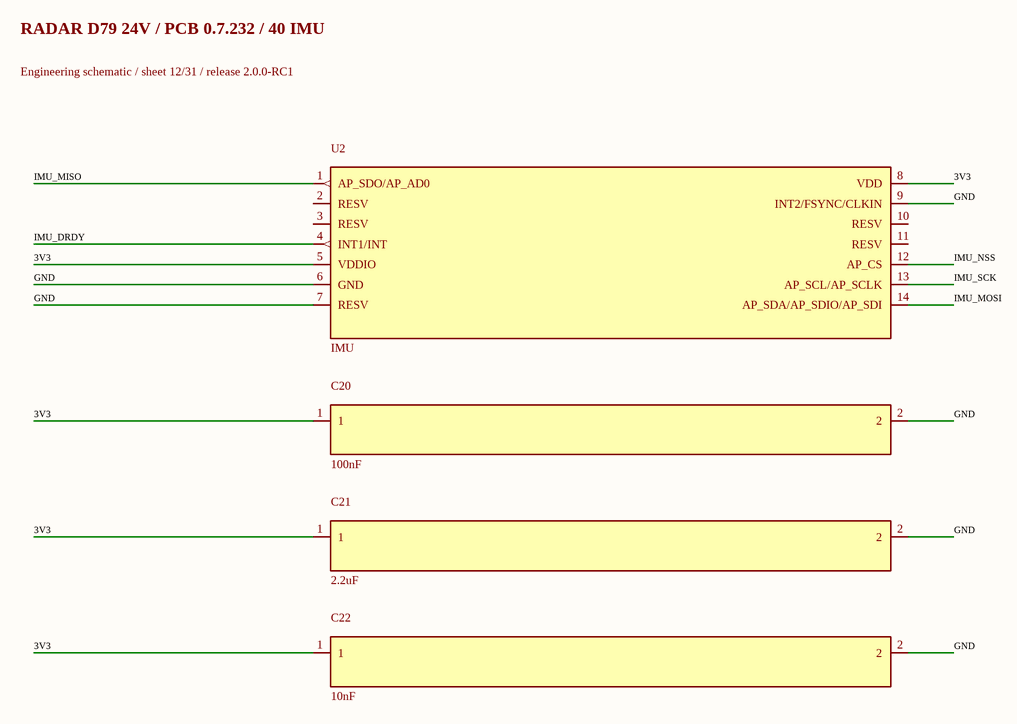
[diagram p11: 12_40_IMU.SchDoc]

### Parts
C20  100nF  [C_0402_1005Metric]
C21  2.2uF  [C_0603_1608Metric]
C22  10nF  [C_0402_1005Metric]
U2  IMU  [ICM-42688-P_LGA14_2.5x3mm_P0.5mm]

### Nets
3V3: C20.1 C21.1 C22.1 U2.5(VDDIO) U2.8(VDD)
GND: C20.2 C21.2 C22.2 U2.6(GND) U2.7(RESV) U2.9(INT2/FSYNC/CLKIN)
IMU_DRDY: U2.4(INT1/INT)
IMU_MISO: U2.1(AP_SDO/AP_AD0)
IMU_MOSI: U2.14(AP_SDA/AP_SDIO/AP_SDI)
IMU_NSS: U2.12(AP_CS)
IMU_SCK: U2.13(AP_SCL/AP_SCLK)

Not connected (* = marked no-connect by the designer): U2 2(RESV) 3(RESV) 10(RESV) 11(RESV)

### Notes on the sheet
- RADAR D79 24V / PCB 0.7.232 / 40 IMU
- Engineering schematic / sheet 12/31 / release 2.0.0-RC1

## Sheet 13_Radar_interfaces_and_QSPI.SchDoc
size 289 x 575 mm
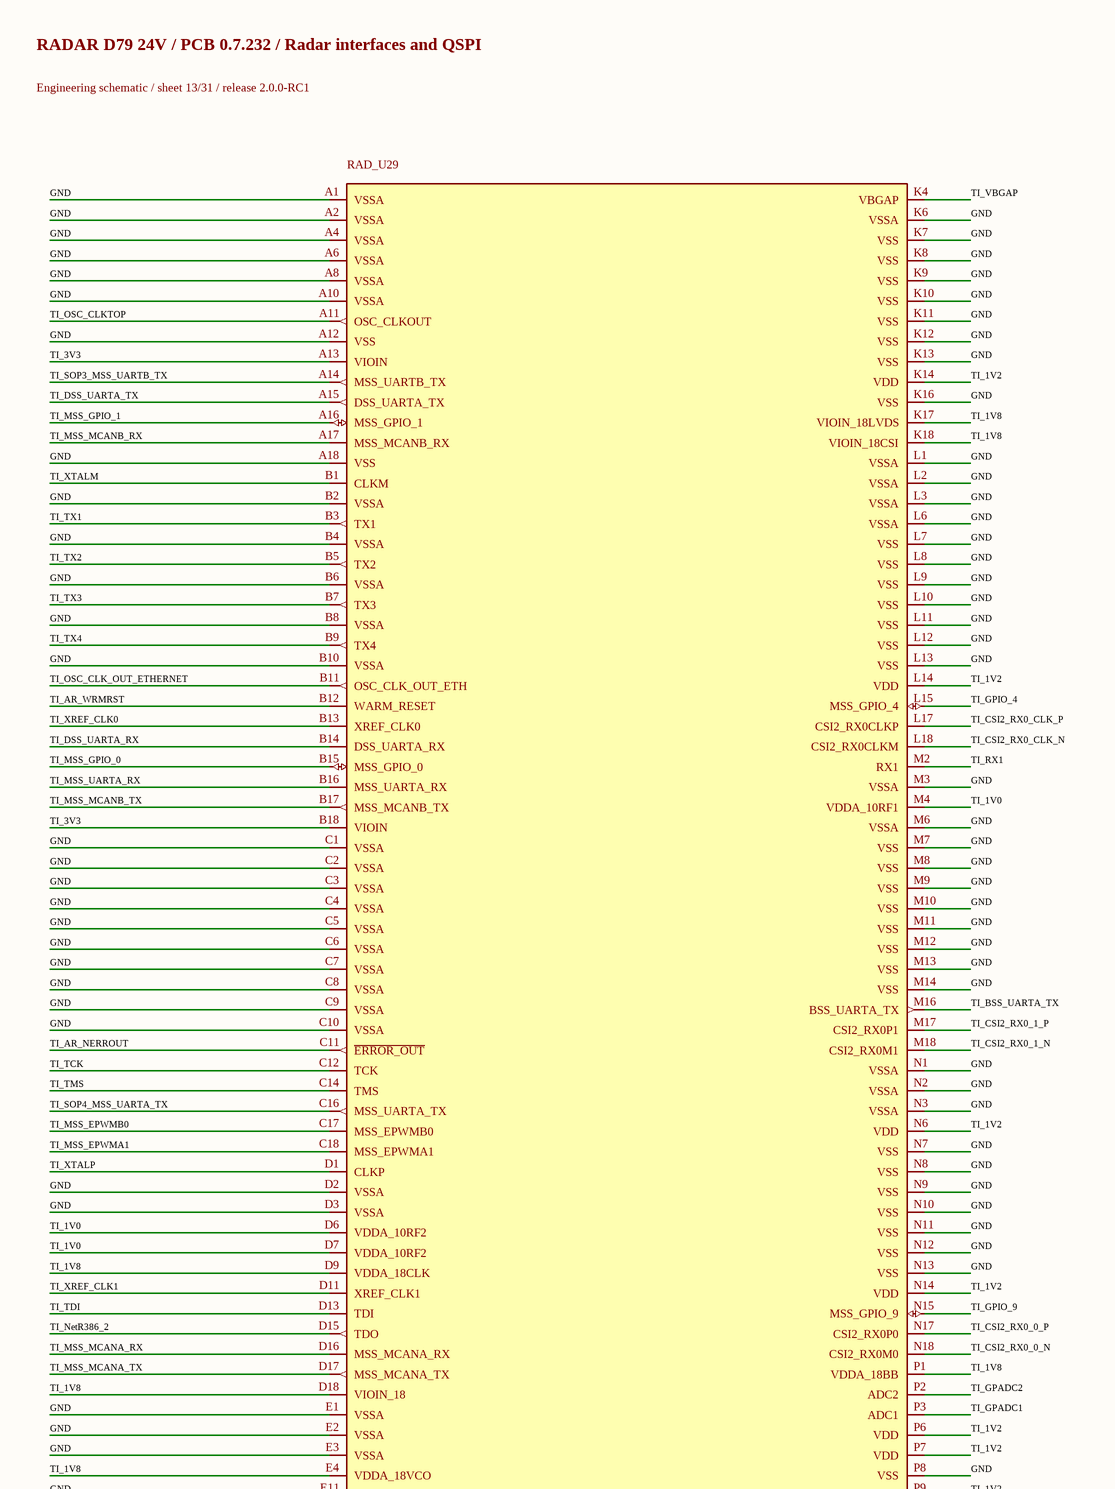
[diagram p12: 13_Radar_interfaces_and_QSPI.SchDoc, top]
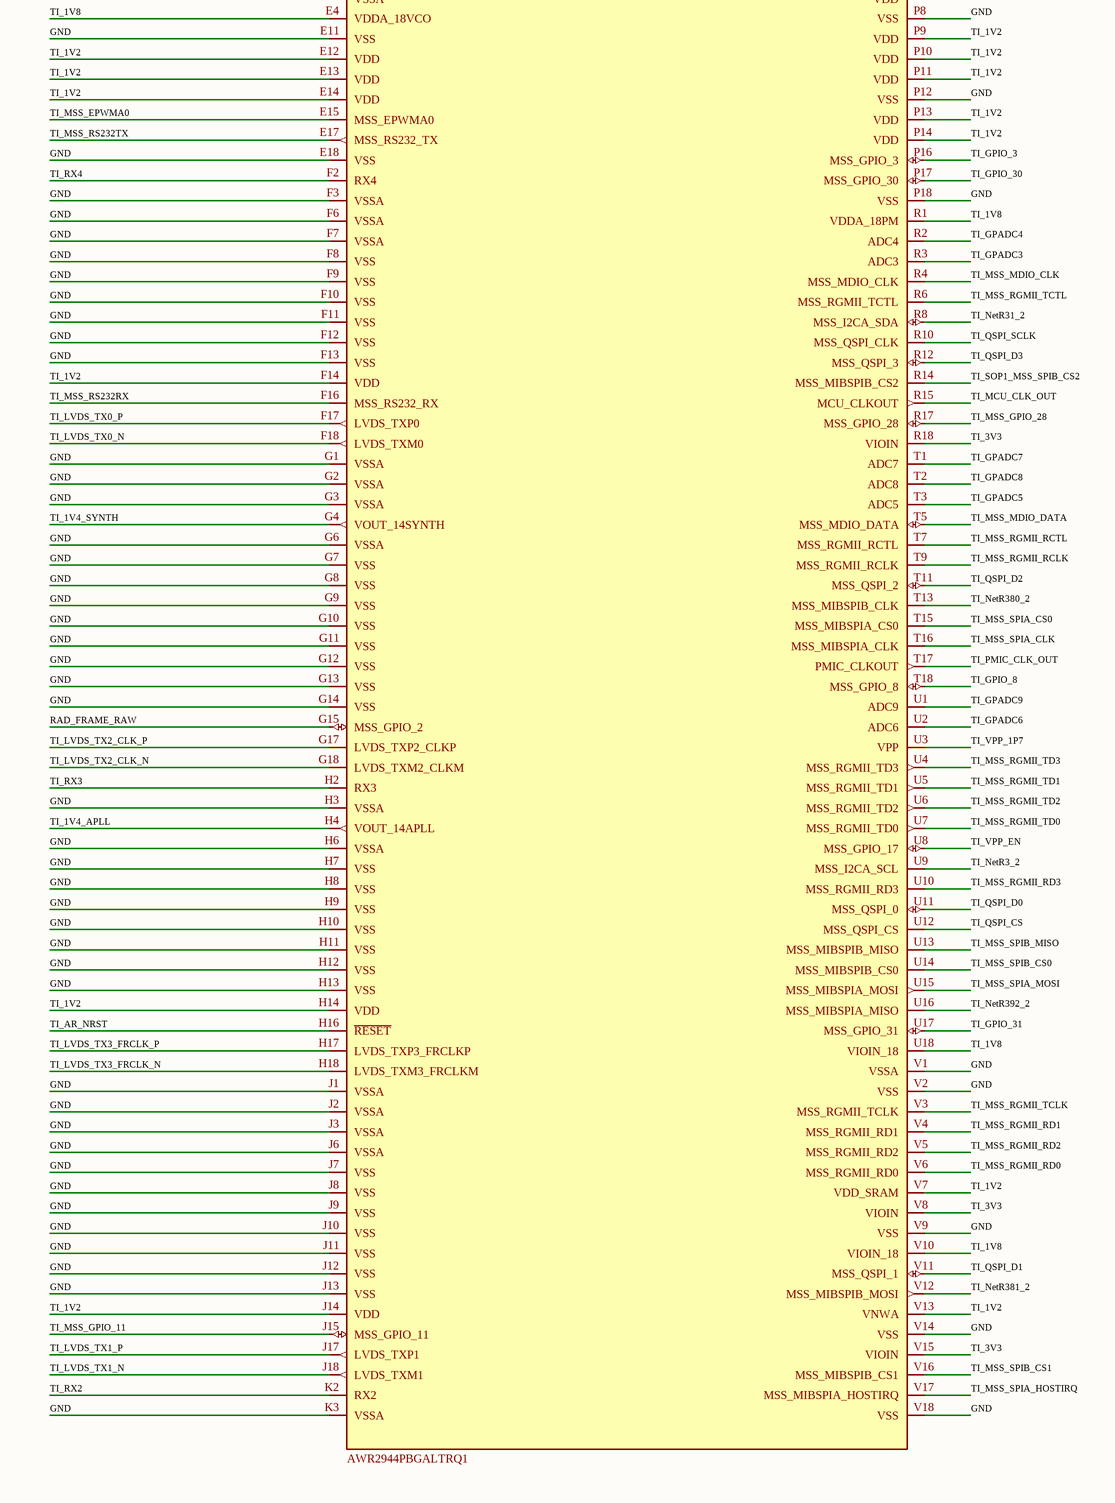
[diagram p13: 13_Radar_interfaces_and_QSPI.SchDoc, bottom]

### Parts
RAD_U29  AWR2944PBGALTRQ1  [ALT0266A-MFG]

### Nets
GND: RAD_U29.A1(VSSA) RAD_U29.A2(VSSA) RAD_U29.A4(VSSA) RAD_U29.A6(VSSA) RAD_U29.A8(VSSA) RAD_U29.A10(VSSA) RAD_U29.A12(VSS) RAD_U29.A18(VSS) RAD_U29.B2(VSSA) RAD_U29.B4(VSSA) RAD_U29.B6(VSSA) RAD_U29.B8(VSSA) RAD_U29.B10(VSSA) RAD_U29.C1(VSSA) RAD_U29.C2(VSSA) RAD_U29.C3(VSSA) RAD_U29.C4(VSSA) RAD_U29.C5(VSSA) RAD_U29.C6(VSSA) RAD_U29.C7(VSSA) RAD_U29.C8(VSSA) RAD_U29.C9(VSSA) RAD_U29.C10(VSSA) RAD_U29.D2(VSSA) RAD_U29.D3(VSSA) RAD_U29.E1(VSSA) RAD_U29.E2(VSSA) RAD_U29.E3(VSSA) RAD_U29.E11(VSS) RAD_U29.E18(VSS) RAD_U29.F3(VSSA) RAD_U29.F6(VSSA) RAD_U29.F7(VSSA) RAD_U29.F8(VSS) RAD_U29.F9(VSS) RAD_U29.F10(VSS) RAD_U29.F11(VSS) RAD_U29.F12(VSS) RAD_U29.F13(VSS) RAD_U29.G1(VSSA) RAD_U29.G2(VSSA) RAD_U29.G3(VSSA) RAD_U29.G6(VSSA) RAD_U29.G7(VSS) RAD_U29.G8(VSS) RAD_U29.G9(VSS) RAD_U29.G10(VSS) RAD_U29.G11(VSS) RAD_U29.G12(VSS) RAD_U29.G13(VSS) RAD_U29.G14(VSS) RAD_U29.H3(VSSA) RAD_U29.H6(VSSA) RAD_U29.H7(VSS) RAD_U29.H8(VSS) RAD_U29.H9(VSS) RAD_U29.H10(VSS) RAD_U29.H11(VSS) RAD_U29.H12(VSS) RAD_U29.H13(VSS) RAD_U29.J1(VSSA) RAD_U29.J2(VSSA) RAD_U29.J3(VSSA) RAD_U29.J6(VSSA) RAD_U29.J7(VSS) RAD_U29.J8(VSS) RAD_U29.J9(VSS) RAD_U29.J10(VSS) RAD_U29.J11(VSS) RAD_U29.J12(VSS) RAD_U29.J13(VSS) RAD_U29.K3(VSSA) RAD_U29.K6(VSSA) RAD_U29.K7(VSS) RAD_U29.K8(VSS) RAD_U29.K9(VSS) RAD_U29.K10(VSS) RAD_U29.K11(VSS) RAD_U29.K12(VSS) RAD_U29.K13(VSS) RAD_U29.K16(VSS) RAD_U29.L1(VSSA) RAD_U29.L2(VSSA) RAD_U29.L3(VSSA) RAD_U29.L6(VSSA) RAD_U29.L7(VSS) RAD_U29.L8(VSS) RAD_U29.L9(VSS) RAD_U29.L10(VSS) RAD_U29.L11(VSS) RAD_U29.L12(VSS) RAD_U29.L13(VSS) RAD_U29.M3(VSSA) RAD_U29.M6(VSSA) RAD_U29.M7(VSS) RAD_U29.M8(VSS) RAD_U29.M9(VSS) RAD_U29.M10(VSS) RAD_U29.M11(VSS) RAD_U29.M12(VSS) RAD_U29.M13(VSS) RAD_U29.M14(VSS) RAD_U29.N1(VSSA) RAD_U29.N2(VSSA) RAD_U29.N3(VSSA) RAD_U29.N7(VSS) RAD_U29.N8(VSS) RAD_U29.N9(VSS) RAD_U29.N10(VSS) RAD_U29.N11(VSS) RAD_U29.N12(VSS) RAD_U29.N13(VSS) RAD_U29.P8(VSS) RAD_U29.P12(VSS) RAD_U29.P18(VSS) RAD_U29.V1(VSSA) RAD_U29.V2(VSS) RAD_U29.V9(VSS) RAD_U29.V14(VSS) RAD_U29.V18(VSS)
RAD_FRAME_RAW: RAD_U29.G15(MSS_GPIO_2)
TI_1V0: RAD_U29.D6(VDDA_10RF2) RAD_U29.D7(VDDA_10RF2) RAD_U29.M4(VDDA_10RF1)
TI_1V2: RAD_U29.E12(VDD) RAD_U29.E13(VDD) RAD_U29.E14(VDD) RAD_U29.F14(VDD) RAD_U29.H14(VDD) RAD_U29.J14(VDD) RAD_U29.K14(VDD) RAD_U29.L14(VDD) RAD_U29.N6(VDD) RAD_U29.N14(VDD) RAD_U29.P6(VDD) RAD_U29.P7(VDD) RAD_U29.P9(VDD) RAD_U29.P10(VDD) RAD_U29.P11(VDD) RAD_U29.P13(VDD) RAD_U29.P14(VDD) RAD_U29.V7(VDD_SRAM) RAD_U29.V13(VNWA)
TI_1V4_APLL: RAD_U29.H4(VOUT_14APLL)
TI_1V4_SYNTH: RAD_U29.G4(VOUT_14SYNTH)
TI_1V8: RAD_U29.D9(VDDA_18CLK) RAD_U29.D18(VIOIN_18) RAD_U29.E4(VDDA_18VCO) RAD_U29.K17(VIOIN_18LVDS) RAD_U29.K18(VIOIN_18CSI) RAD_U29.P1(VDDA_18BB) RAD_U29.R1(VDDA_18PM) RAD_U29.U18(VIOIN_18) RAD_U29.V10(VIOIN_18)
TI_3V3: RAD_U29.A13(VIOIN) RAD_U29.B18(VIOIN) RAD_U29.R18(VIOIN) RAD_U29.V8(VIOIN) RAD_U29.V15(VIOIN)
TI_AR_NERROUT: RAD_U29.C11(~{ERROR_OUT})
TI_AR_NRST: RAD_U29.H16(~{RESET})
TI_AR_WRMRST: RAD_U29.B12(WARM_RESET)
TI_BSS_UARTA_TX: RAD_U29.M16(BSS_UARTA_TX)
TI_CSI2_RX0_0_N: RAD_U29.N18(CSI2_RX0M0)
TI_CSI2_RX0_0_P: RAD_U29.N17(CSI2_RX0P0)
TI_CSI2_RX0_1_N: RAD_U29.M18(CSI2_RX0M1)
TI_CSI2_RX0_1_P: RAD_U29.M17(CSI2_RX0P1)
TI_CSI2_RX0_CLK_N: RAD_U29.L18(CSI2_RX0CLKM)
TI_CSI2_RX0_CLK_P: RAD_U29.L17(CSI2_RX0CLKP)
TI_DSS_UARTA_RX: RAD_U29.B14(DSS_UARTA_RX)
TI_DSS_UARTA_TX: RAD_U29.A15(DSS_UARTA_TX)
TI_GPADC1: RAD_U29.P3(ADC1)
TI_GPADC2: RAD_U29.P2(ADC2)
TI_GPADC3: RAD_U29.R3(ADC3)
TI_GPADC4: RAD_U29.R2(ADC4)
TI_GPADC5: RAD_U29.T3(ADC5)
TI_GPADC6: RAD_U29.U2(ADC6)
TI_GPADC7: RAD_U29.T1(ADC7)
TI_GPADC8: RAD_U29.T2(ADC8)
TI_GPADC9: RAD_U29.U1(ADC9)
TI_GPIO_3: RAD_U29.P16(MSS_GPIO_3)
TI_GPIO_4: RAD_U29.L15(MSS_GPIO_4)
TI_GPIO_8: RAD_U29.T18(MSS_GPIO_8)
TI_GPIO_9: RAD_U29.N15(MSS_GPIO_9)
TI_GPIO_30: RAD_U29.P17(MSS_GPIO_30)
TI_GPIO_31: RAD_U29.U17(MSS_GPIO_31)
TI_LVDS_TX0_N: RAD_U29.F18(LVDS_TXM0)
TI_LVDS_TX0_P: RAD_U29.F17(LVDS_TXP0)
TI_LVDS_TX1_N: RAD_U29.J18(LVDS_TXM1)
TI_LVDS_TX1_P: RAD_U29.J17(LVDS_TXP1)
TI_LVDS_TX2_CLK_N: RAD_U29.G18(LVDS_TXM2_CLKM)
TI_LVDS_TX2_CLK_P: RAD_U29.G17(LVDS_TXP2_CLKP)
TI_LVDS_TX3_FRCLK_N: RAD_U29.H18(LVDS_TXM3_FRCLKM)
TI_LVDS_TX3_FRCLK_P: RAD_U29.H17(LVDS_TXP3_FRCLKP)
TI_MCU_CLK_OUT: RAD_U29.R15(MCU_CLKOUT)
TI_MSS_EPWMA0: RAD_U29.E15(MSS_EPWMA0)
TI_MSS_EPWMA1: RAD_U29.C18(MSS_EPWMA1)
TI_MSS_EPWMB0: RAD_U29.C17(MSS_EPWMB0)
TI_MSS_GPIO_0: RAD_U29.B15(MSS_GPIO_0)
TI_MSS_GPIO_1: RAD_U29.A16(MSS_GPIO_1)
TI_MSS_GPIO_11: RAD_U29.J15(MSS_GPIO_11)
TI_MSS_GPIO_28: RAD_U29.R17(MSS_GPIO_28)
TI_MSS_MCANA_RX: RAD_U29.D16(MSS_MCANA_RX)
TI_MSS_MCANA_TX: RAD_U29.D17(MSS_MCANA_TX)
TI_MSS_MCANB_RX: RAD_U29.A17(MSS_MCANB_RX)
TI_MSS_MCANB_TX: RAD_U29.B17(MSS_MCANB_TX)
TI_MSS_MDIO_CLK: RAD_U29.R4(MSS_MDIO_CLK)
TI_MSS_MDIO_DATA: RAD_U29.T5(MSS_MDIO_DATA)
TI_MSS_RGMII_RCLK: RAD_U29.T9(MSS_RGMII_RCLK)
TI_MSS_RGMII_RCTL: RAD_U29.T7(MSS_RGMII_RCTL)
TI_MSS_RGMII_RD0: RAD_U29.V6(MSS_RGMII_RD0)
TI_MSS_RGMII_RD1: RAD_U29.V4(MSS_RGMII_RD1)
TI_MSS_RGMII_RD2: RAD_U29.V5(MSS_RGMII_RD2)
TI_MSS_RGMII_RD3: RAD_U29.U10(MSS_RGMII_RD3)
TI_MSS_RGMII_TCLK: RAD_U29.V3(MSS_RGMII_TCLK)
TI_MSS_RGMII_TCTL: RAD_U29.R6(MSS_RGMII_TCTL)
TI_MSS_RGMII_TD0: RAD_U29.U7(MSS_RGMII_TD0)
TI_MSS_RGMII_TD1: RAD_U29.U5(MSS_RGMII_TD1)
TI_MSS_RGMII_TD2: RAD_U29.U6(MSS_RGMII_TD2)
TI_MSS_RGMII_TD3: RAD_U29.U4(MSS_RGMII_TD3)
TI_MSS_RS232RX: RAD_U29.F16(MSS_RS232_RX)
TI_MSS_RS232TX: RAD_U29.E17(MSS_RS232_TX)
TI_MSS_SPIA_CLK: RAD_U29.T16(MSS_MIBSPIA_CLK)
TI_MSS_SPIA_CS0: RAD_U29.T15(MSS_MIBSPIA_CS0)
TI_MSS_SPIA_HOSTIRQ: RAD_U29.V17(MSS_MIBSPIA_HOSTIRQ)
TI_MSS_SPIA_MOSI: RAD_U29.U15(MSS_MIBSPIA_MOSI)
TI_MSS_SPIB_CS0: RAD_U29.U14(MSS_MIBSPIB_CS0)
TI_MSS_SPIB_CS1: RAD_U29.V16(MSS_MIBSPIB_CS1)
TI_MSS_SPIB_MISO: RAD_U29.U13(MSS_MIBSPIB_MISO)
TI_MSS_UARTA_RX: RAD_U29.B16(MSS_UARTA_RX)
TI_NetR3_2: RAD_U29.U9(MSS_I2CA_SCL)
TI_NetR31_2: RAD_U29.R8(MSS_I2CA_SDA)
TI_NetR380_2: RAD_U29.T13(MSS_MIBSPIB_CLK)
TI_NetR381_2: RAD_U29.V12(MSS_MIBSPIB_MOSI)
TI_NetR386_2: RAD_U29.D15(TDO)
TI_NetR392_2: RAD_U29.U16(MSS_MIBSPIA_MISO)
TI_OSC_CLK_OUT_ETHERNET: RAD_U29.B11(OSC_CLK_OUT_ETH)
TI_OSC_CLKTOP: RAD_U29.A11(OSC_CLKOUT)
TI_PMIC_CLK_OUT: RAD_U29.T17(PMIC_CLKOUT)
TI_QSPI_CS: RAD_U29.U12(MSS_QSPI_CS)
TI_QSPI_D0: RAD_U29.U11(MSS_QSPI_0)
TI_QSPI_D1: RAD_U29.V11(MSS_QSPI_1)
TI_QSPI_D2: RAD_U29.T11(MSS_QSPI_2)
TI_QSPI_D3: RAD_U29.R12(MSS_QSPI_3)
TI_QSPI_SCLK: RAD_U29.R10(MSS_QSPI_CLK)
TI_RX1: RAD_U29.M2(RX1)
TI_RX2: RAD_U29.K2(RX2)
TI_RX3: RAD_U29.H2(RX3)
TI_RX4: RAD_U29.F2(RX4)
TI_SOP1_MSS_SPIB_CS2: RAD_U29.R14(MSS_MIBSPIB_CS2)
TI_SOP3_MSS_UARTB_TX: RAD_U29.A14(MSS_UARTB_TX)
TI_SOP4_MSS_UARTA_TX: RAD_U29.C16(MSS_UARTA_TX)
TI_TCK: RAD_U29.C12(TCK)
TI_TDI: RAD_U29.D13(TDI)
TI_TMS: RAD_U29.C14(TMS)
TI_TX1: RAD_U29.B3(TX1)
TI_TX2: RAD_U29.B5(TX2)
TI_TX3: RAD_U29.B7(TX3)
TI_TX4: RAD_U29.B9(TX4)
TI_VBGAP: RAD_U29.K4(VBGAP)
TI_VPP_1P7: RAD_U29.U3(VPP)
TI_VPP_EN: RAD_U29.U8(MSS_GPIO_17)
TI_XREF_CLK0: RAD_U29.B13(XREF_CLK0)
TI_XREF_CLK1: RAD_U29.D11(XREF_CLK1)
TI_XTALM: RAD_U29.B1(CLKM)
TI_XTALP: RAD_U29.D1(CLKP)

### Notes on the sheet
- RADAR D79 24V / PCB 0.7.232 / Radar interfaces and QSPI
- Engineering schematic / sheet 13/31 / release 2.0.0-RC1

## Sheet 14_Radar_interfaces_and_QSPI.SchDoc
size 289 x 396 mm
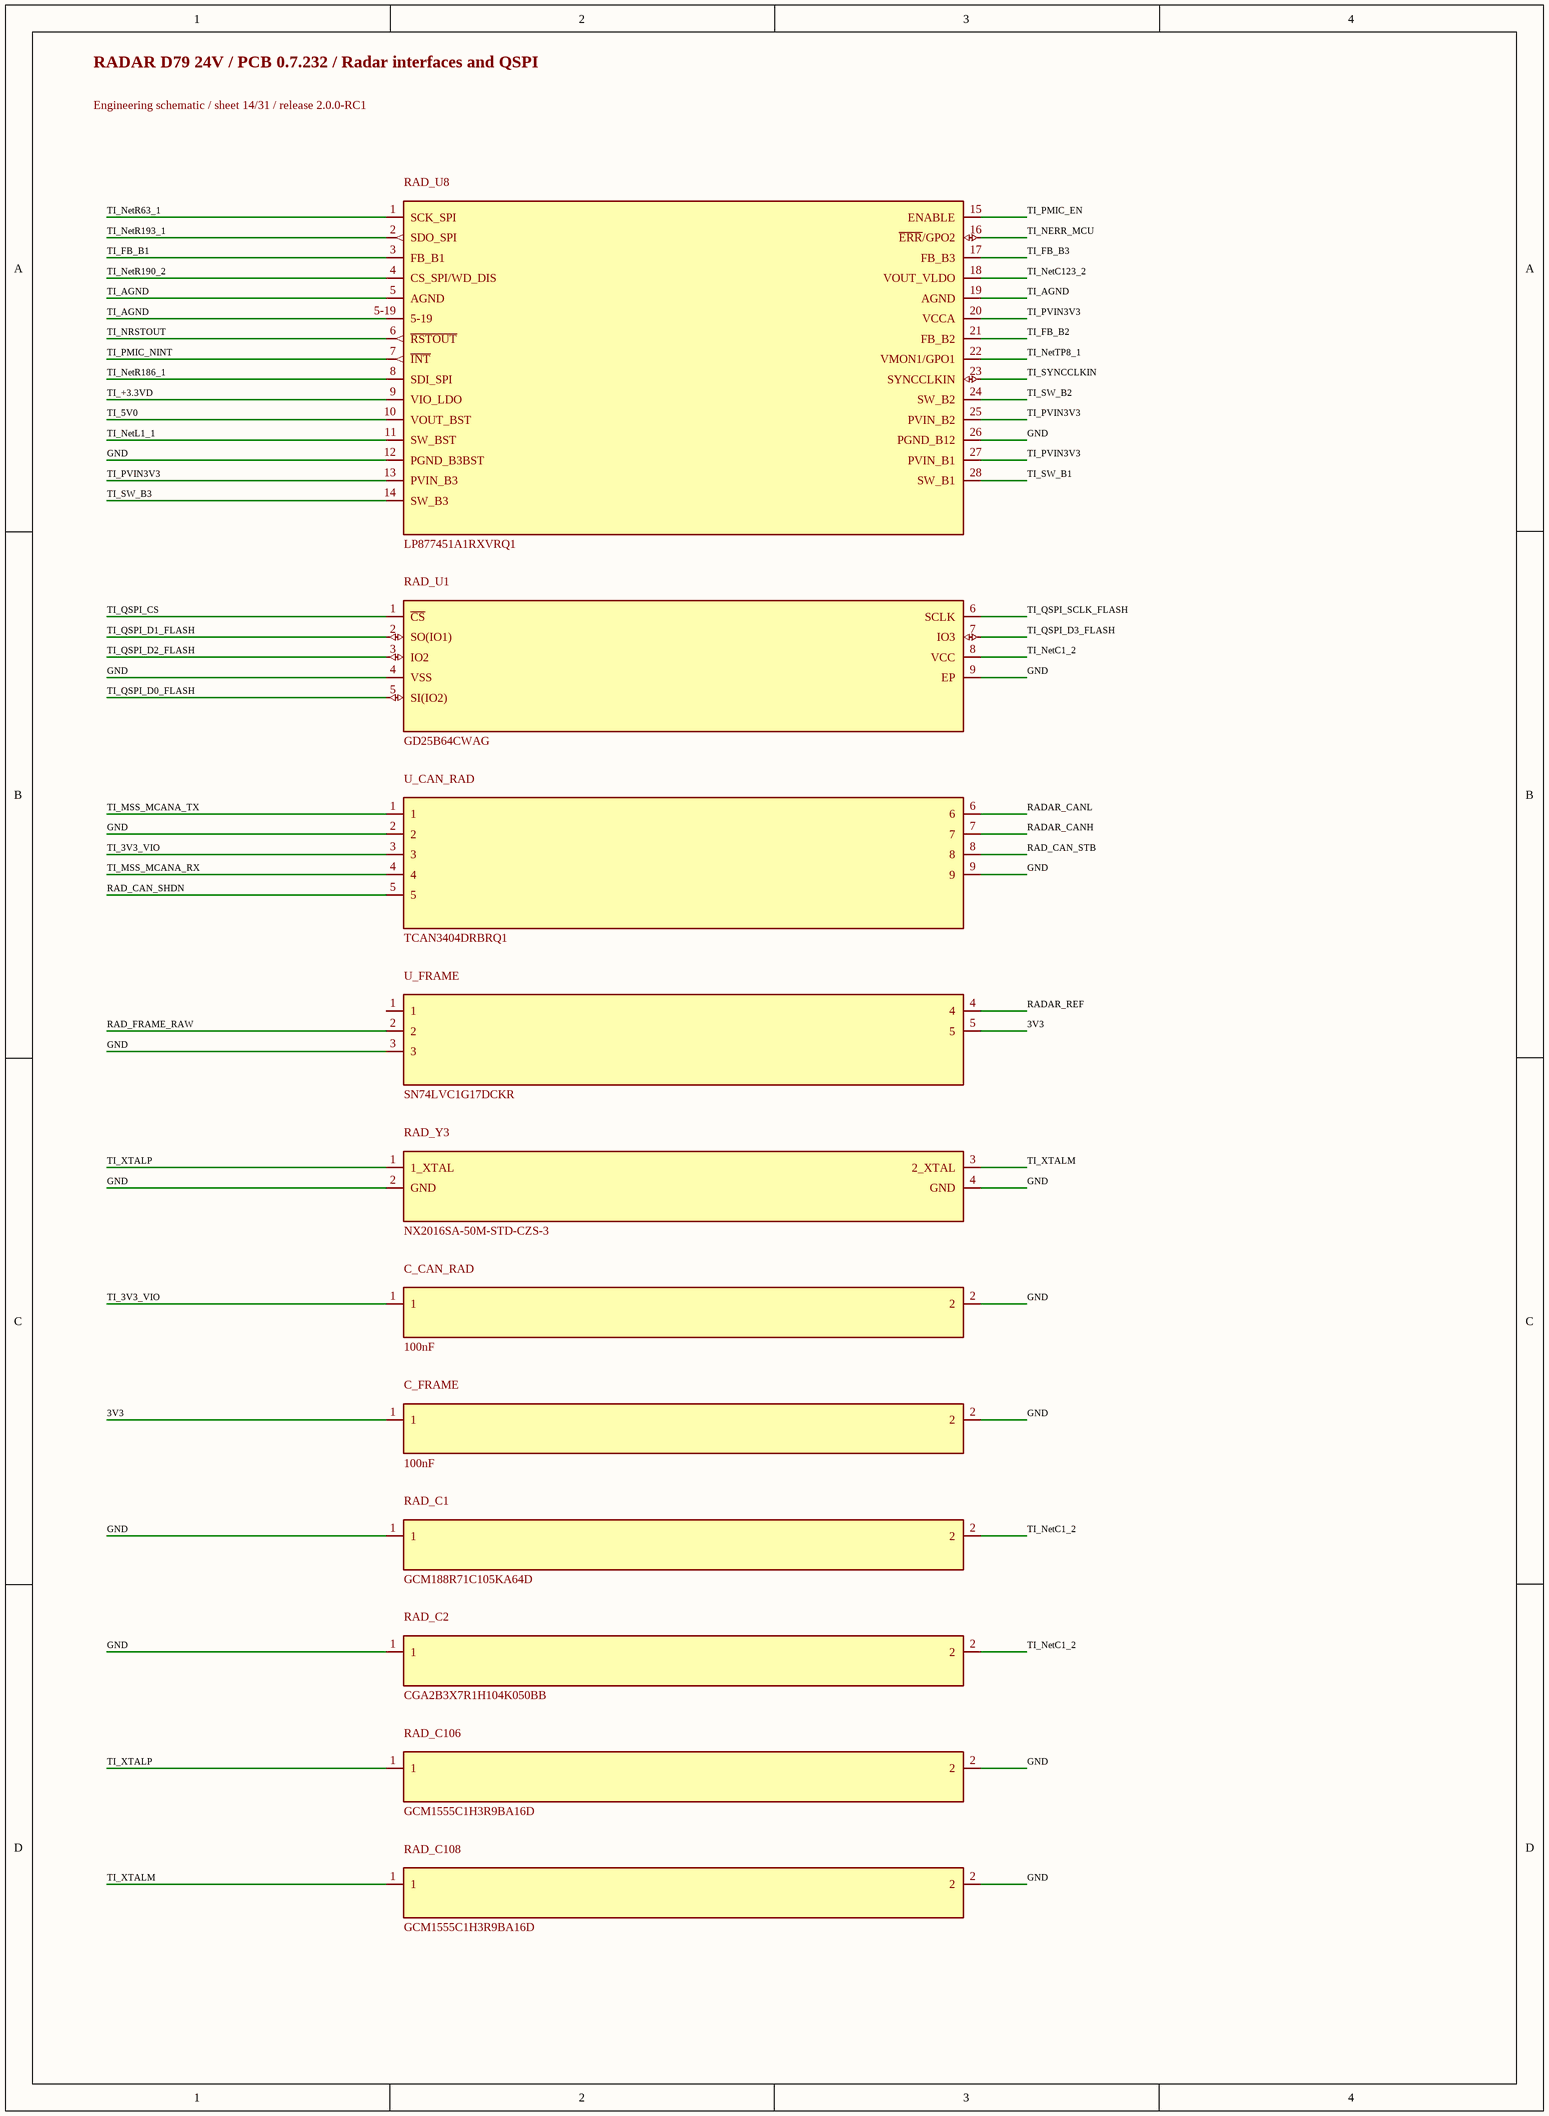
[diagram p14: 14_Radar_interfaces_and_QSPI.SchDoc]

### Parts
C_CAN_RAD  100nF  [C_0402_1005Metric]
C_FRAME  100nF  [C_0402_1005Metric]
RAD_C1  GCM188R71C105KA64D  [0603L]
RAD_C2  CGA2B3X7R1H104K050BB  [0402L]
RAD_C106  GCM1555C1H3R9BA16D  [FP-GCM1555C1H3R9BA16D_0402-MFG]
RAD_C108  GCM1555C1H3R9BA16D  [FP-GCM1555C1H3R9BA16D_0402-MFG]
RAD_U1  GD25B64CWAG  [FP-GD25B64CWAG_WSON8-IPC_C]
RAD_U8  LP877451A1RXVRQ1  [RXV0028A-MFG]
RAD_Y3  NX2016SA-50M-STD-CZS-3  [FP-NX2016SA-50M-STD-CZS-3_SMT4_2MM0_1MM6-MFG]
U_CAN_RAD  TCAN3404DRBRQ1  [Texas_DRB0008A]
U_FRAME  SN74LVC1G17DCKR  [DCK0005A_N]

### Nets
3V3: C_FRAME.1 U_FRAME.5
GND: C_CAN_RAD.2 C_FRAME.2 RAD_C1.1 RAD_C2.1 RAD_C106.2 RAD_C108.2 RAD_U1.4(VSS) RAD_U1.9(EP) RAD_U8.12(PGND_B3BST) RAD_U8.26(PGND_B12) RAD_Y3.2(GND) RAD_Y3.4(GND) U_CAN_RAD.2 U_CAN_RAD.9 U_FRAME.3
RAD_CAN_SHDN: U_CAN_RAD.5
RAD_CAN_STB: U_CAN_RAD.8
RAD_FRAME_RAW: U_FRAME.2
RADAR_CANH: U_CAN_RAD.7
RADAR_CANL: U_CAN_RAD.6
RADAR_REF: U_FRAME.4
TI_3V3_VIO: C_CAN_RAD.1 U_CAN_RAD.3
TI_5V0: RAD_U8.10(VOUT_BST)
TI_+3.3VD: RAD_U8.9(VIO_LDO)
TI_AGND: RAD_U8.5(AGND) RAD_U8.5-19 RAD_U8.19(AGND)
TI_FB_B1: RAD_U8.3(FB_B1)
TI_FB_B2: RAD_U8.21(FB_B2)
TI_FB_B3: RAD_U8.17(FB_B3)
TI_MSS_MCANA_RX: U_CAN_RAD.4
TI_MSS_MCANA_TX: U_CAN_RAD.1
TI_NERR_MCU: RAD_U8.16(~{ERR}/GPO2)
TI_NetC1_2: RAD_C1.2 RAD_C2.2 RAD_U1.8(VCC)
TI_NetC123_2: RAD_U8.18(VOUT_VLDO)
TI_NetL1_1: RAD_U8.11(SW_BST)
TI_NetR63_1: RAD_U8.1(SCK_SPI)
TI_NetR186_1: RAD_U8.8(SDI_SPI)
TI_NetR190_2: RAD_U8.4(CS_SPI/WD_DIS)
TI_NetR193_1: RAD_U8.2(SDO_SPI)
TI_NetTP8_1: RAD_U8.22(VMON1/GPO1)
TI_NRSTOUT: RAD_U8.6(~{RSTOUT})
TI_PMIC_EN: RAD_U8.15(ENABLE)
TI_PMIC_NINT: RAD_U8.7(~{INT})
TI_PVIN3V3: RAD_U8.13(PVIN_B3) RAD_U8.20(VCCA) RAD_U8.25(PVIN_B2) RAD_U8.27(PVIN_B1)
TI_QSPI_CS: RAD_U1.1(~{CS})
TI_QSPI_D0_FLASH: RAD_U1.5(SI(IO2))
TI_QSPI_D1_FLASH: RAD_U1.2(SO(IO1))
TI_QSPI_D2_FLASH: RAD_U1.3(IO2)
TI_QSPI_D3_FLASH: RAD_U1.7(IO3)
TI_QSPI_SCLK_FLASH: RAD_U1.6(SCLK)
TI_SW_B1: RAD_U8.28(SW_B1)
TI_SW_B2: RAD_U8.24(SW_B2)
TI_SW_B3: RAD_U8.14(SW_B3)
TI_SYNCCLKIN: RAD_U8.23(SYNCCLKIN)
TI_XTALM: RAD_C108.1 RAD_Y3.3(2_XTAL)
TI_XTALP: RAD_C106.1 RAD_Y3.1(1_XTAL)

Not connected (* = marked no-connect by the designer): U_FRAME 1

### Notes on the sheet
- RADAR D79 24V / PCB 0.7.232 / Radar interfaces and QSPI
- Engineering schematic / sheet 14/31 / release 2.0.0-RC1

## Sheet 15_Radar_interfaces_and_QSPI.SchDoc
size 289 x 396 mm
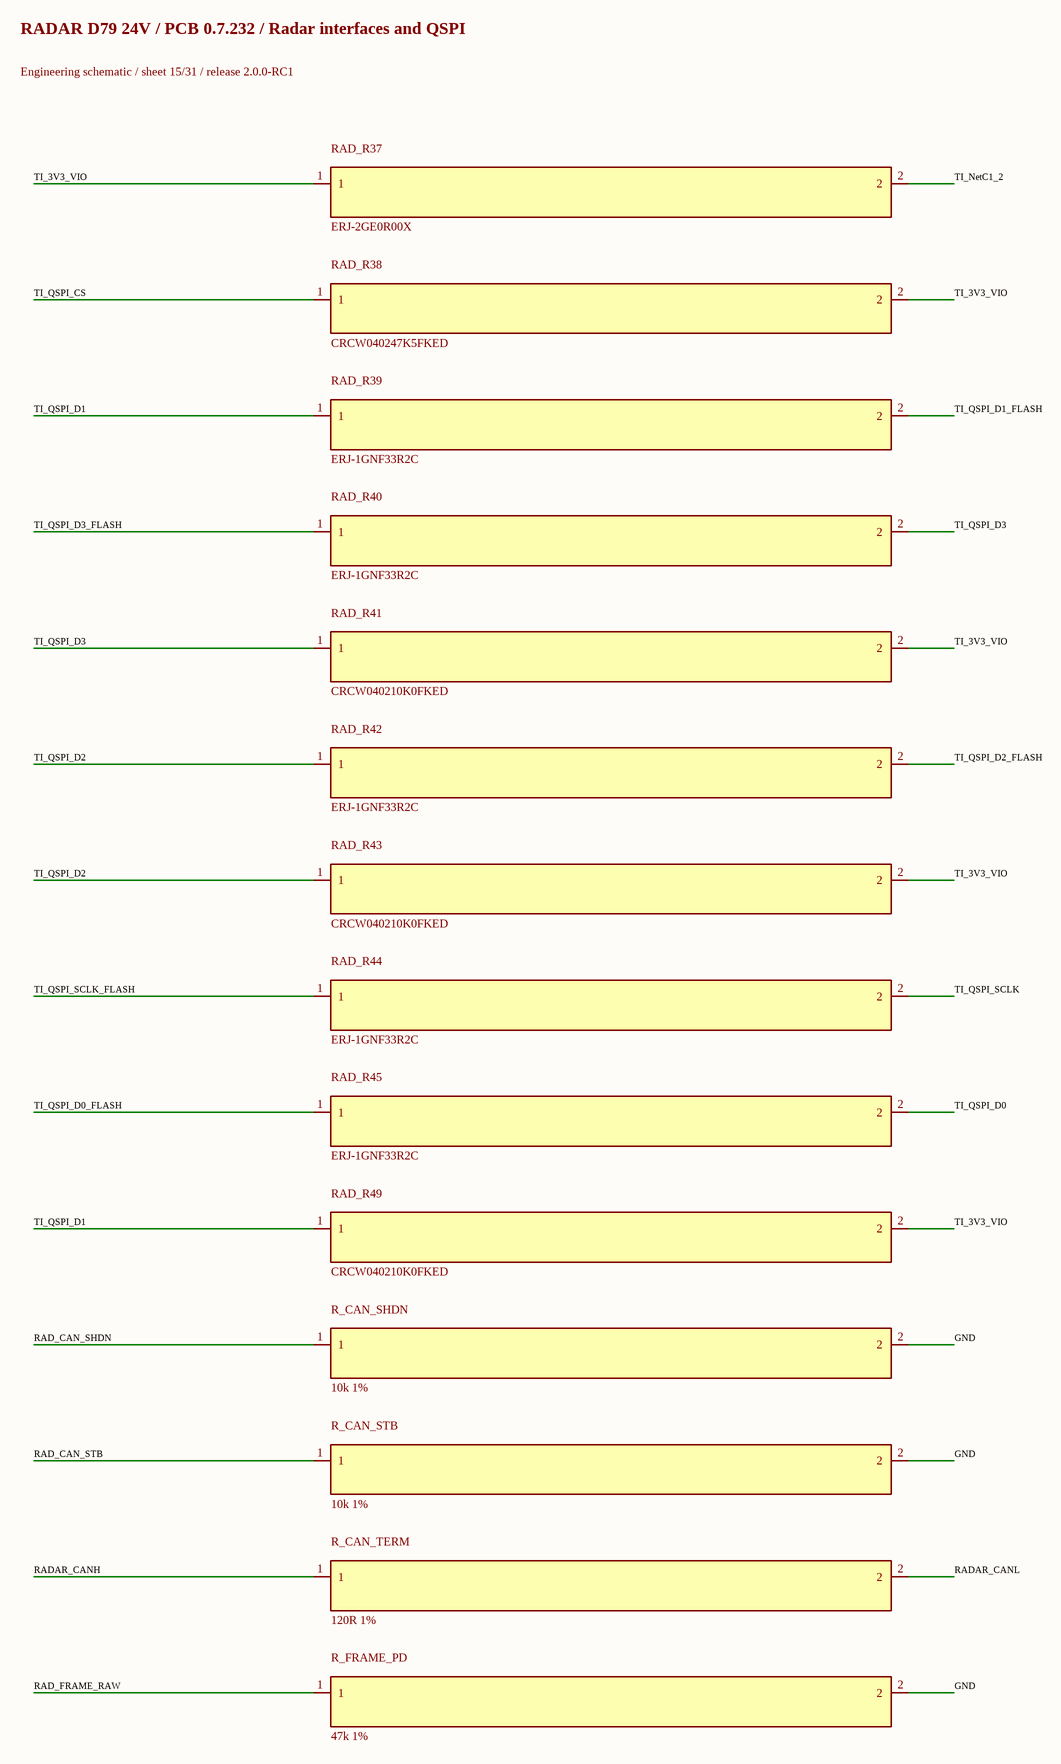
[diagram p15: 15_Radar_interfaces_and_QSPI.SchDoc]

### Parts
R_CAN_SHDN  10k 1%  [R_0603_1608Metric]
R_CAN_STB  10k 1%  [R_0603_1608Metric]
R_CAN_TERM  120R 1%  [R_0603_1608Metric]
R_FRAME_PD  47k 1%  [R_0603_1608Metric]
RAD_R37  ERJ-2GE0R00X  [0402L]
RAD_R38  CRCW040247K5FKED  [0402L]
RAD_R39  ERJ-1GNF33R2C  [FP-ERJ-1GNF33R2C_0201-MFG]
RAD_R40  ERJ-1GNF33R2C  [FP-ERJ-1GNF33R2C_0201-MFG]
RAD_R41  CRCW040210K0FKED  [0402L]
RAD_R42  ERJ-1GNF33R2C  [FP-ERJ-1GNF33R2C_0201-MFG]
RAD_R43  CRCW040210K0FKED  [0402L]
RAD_R44  ERJ-1GNF33R2C  [FP-ERJ-1GNF33R2C_0201-MFG]
RAD_R45  ERJ-1GNF33R2C  [FP-ERJ-1GNF33R2C_0201-MFG]
RAD_R49  CRCW040210K0FKED  [0402L]

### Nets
GND: R_CAN_SHDN.2 R_CAN_STB.2 R_FRAME_PD.2
RAD_CAN_SHDN: R_CAN_SHDN.1
RAD_CAN_STB: R_CAN_STB.1
RAD_FRAME_RAW: R_FRAME_PD.1
RADAR_CANH: R_CAN_TERM.1
RADAR_CANL: R_CAN_TERM.2
TI_3V3_VIO: RAD_R37.1 RAD_R38.2 RAD_R41.2 RAD_R43.2 RAD_R49.2
TI_NetC1_2: RAD_R37.2
TI_QSPI_CS: RAD_R38.1
TI_QSPI_D0: RAD_R45.2
TI_QSPI_D0_FLASH: RAD_R45.1
TI_QSPI_D1: RAD_R39.1 RAD_R49.1
TI_QSPI_D1_FLASH: RAD_R39.2
TI_QSPI_D2: RAD_R42.1 RAD_R43.1
TI_QSPI_D2_FLASH: RAD_R42.2
TI_QSPI_D3: RAD_R40.2 RAD_R41.1
TI_QSPI_D3_FLASH: RAD_R40.1
TI_QSPI_SCLK: RAD_R44.2
TI_QSPI_SCLK_FLASH: RAD_R44.1

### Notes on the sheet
- RADAR D79 24V / PCB 0.7.232 / Radar interfaces and QSPI
- Engineering schematic / sheet 15/31 / release 2.0.0-RC1

## Sheet 16_Radar_service_USB_and_boot.SchDoc
size 289 x 396 mm
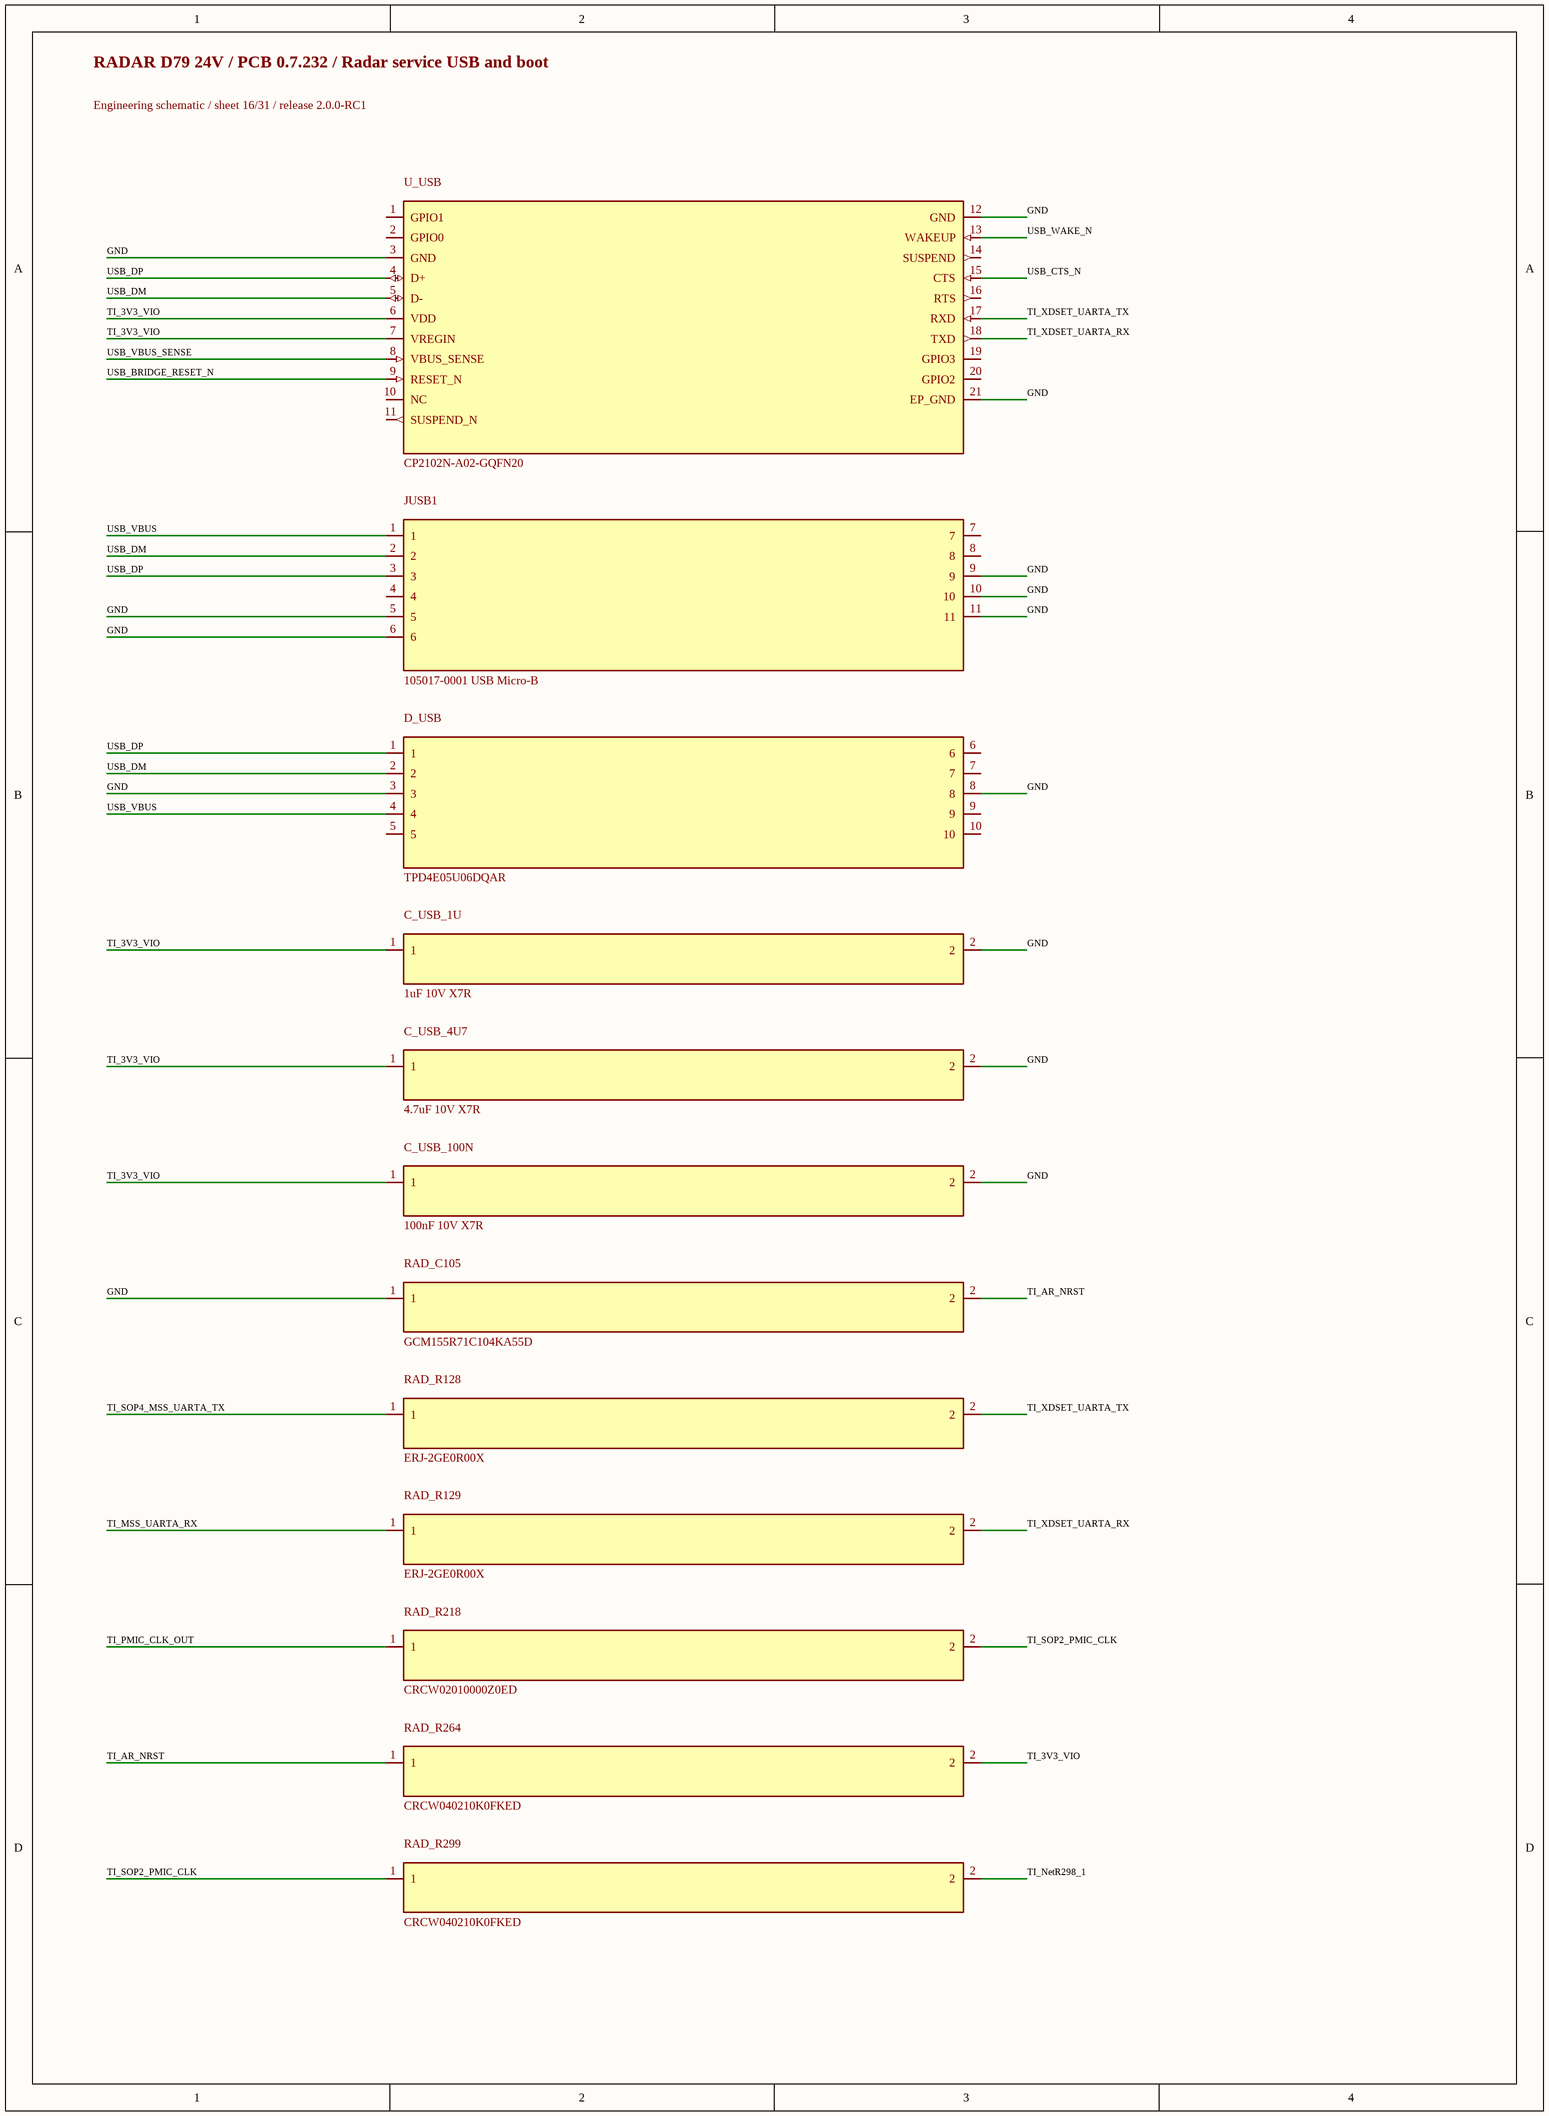
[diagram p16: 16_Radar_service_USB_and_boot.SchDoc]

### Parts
C_USB_1U  1uF 10V X7R  [C_0603_1608Metric]
C_USB_4U7  4.7uF 10V X7R  [C_0603_1608Metric]
C_USB_100N  100nF 10V X7R  [C_0402_1005Metric]
D_USB  TPD4E05U06DQAR  [USON-10_2.5x1.0mm_P0.5mm]
JUSB1  105017-0001 USB Micro-B  [CONN_105017-0001]
RAD_C105  GCM155R71C104KA55D  [0402L]
RAD_R128  ERJ-2GE0R00X  [0402L]
RAD_R129  ERJ-2GE0R00X  [0402L]
RAD_R218  CRCW02010000Z0ED  [0201L]
RAD_R264  CRCW040210K0FKED  [0402L]
RAD_R299  CRCW040210K0FKED  [0402L]
U_USB  CP2102N-A02-GQFN20  [CP2102N_QFN20_3x3_EP_Rev1p5]

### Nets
GND: C_USB_1U.2 C_USB_4U7.2 C_USB_100N.2 D_USB.3 D_USB.8 JUSB1.5 JUSB1.6 JUSB1.9 JUSB1.10 JUSB1.11 RAD_C105.1 U_USB.3(GND) U_USB.12(GND) U_USB.21(EP_GND)
TI_3V3_VIO: C_USB_1U.1 C_USB_4U7.1 C_USB_100N.1 RAD_R264.2 U_USB.6(VDD) U_USB.7(VREGIN)
TI_AR_NRST: RAD_C105.2 RAD_R264.1
TI_MSS_UARTA_RX: RAD_R129.1
TI_NetR298_1: RAD_R299.2
TI_PMIC_CLK_OUT: RAD_R218.1
TI_SOP2_PMIC_CLK: RAD_R218.2 RAD_R299.1
TI_SOP4_MSS_UARTA_TX: RAD_R128.1
TI_XDSET_UARTA_RX: RAD_R129.2 U_USB.18(TXD)
TI_XDSET_UARTA_TX: RAD_R128.2 U_USB.17(RXD)
USB_BRIDGE_RESET_N: U_USB.9(RESET_N)
USB_CTS_N: U_USB.15(CTS)
USB_DM: D_USB.2 JUSB1.2 U_USB.5(D-)
USB_DP: D_USB.1 JUSB1.3 U_USB.4(D+)
USB_VBUS: D_USB.4 JUSB1.1
USB_VBUS_SENSE: U_USB.8(VBUS_SENSE)
USB_WAKE_N: U_USB.13(WAKEUP)

Not connected (* = marked no-connect by the designer): D_USB 5 6 7 9 10; JUSB1 4 7 8; U_USB 1(GPIO1) 2(GPIO0) 10(NC) 11(SUSPEND_N) 14(SUSPEND) 16(RTS) 19(GPIO3) 20(GPIO2)

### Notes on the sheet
- RADAR D79 24V / PCB 0.7.232 / Radar service USB and boot
- Engineering schematic / sheet 16/31 / release 2.0.0-RC1

## Sheet 17_Radar_service_USB_and_boot.SchDoc
size 289 x 400 mm
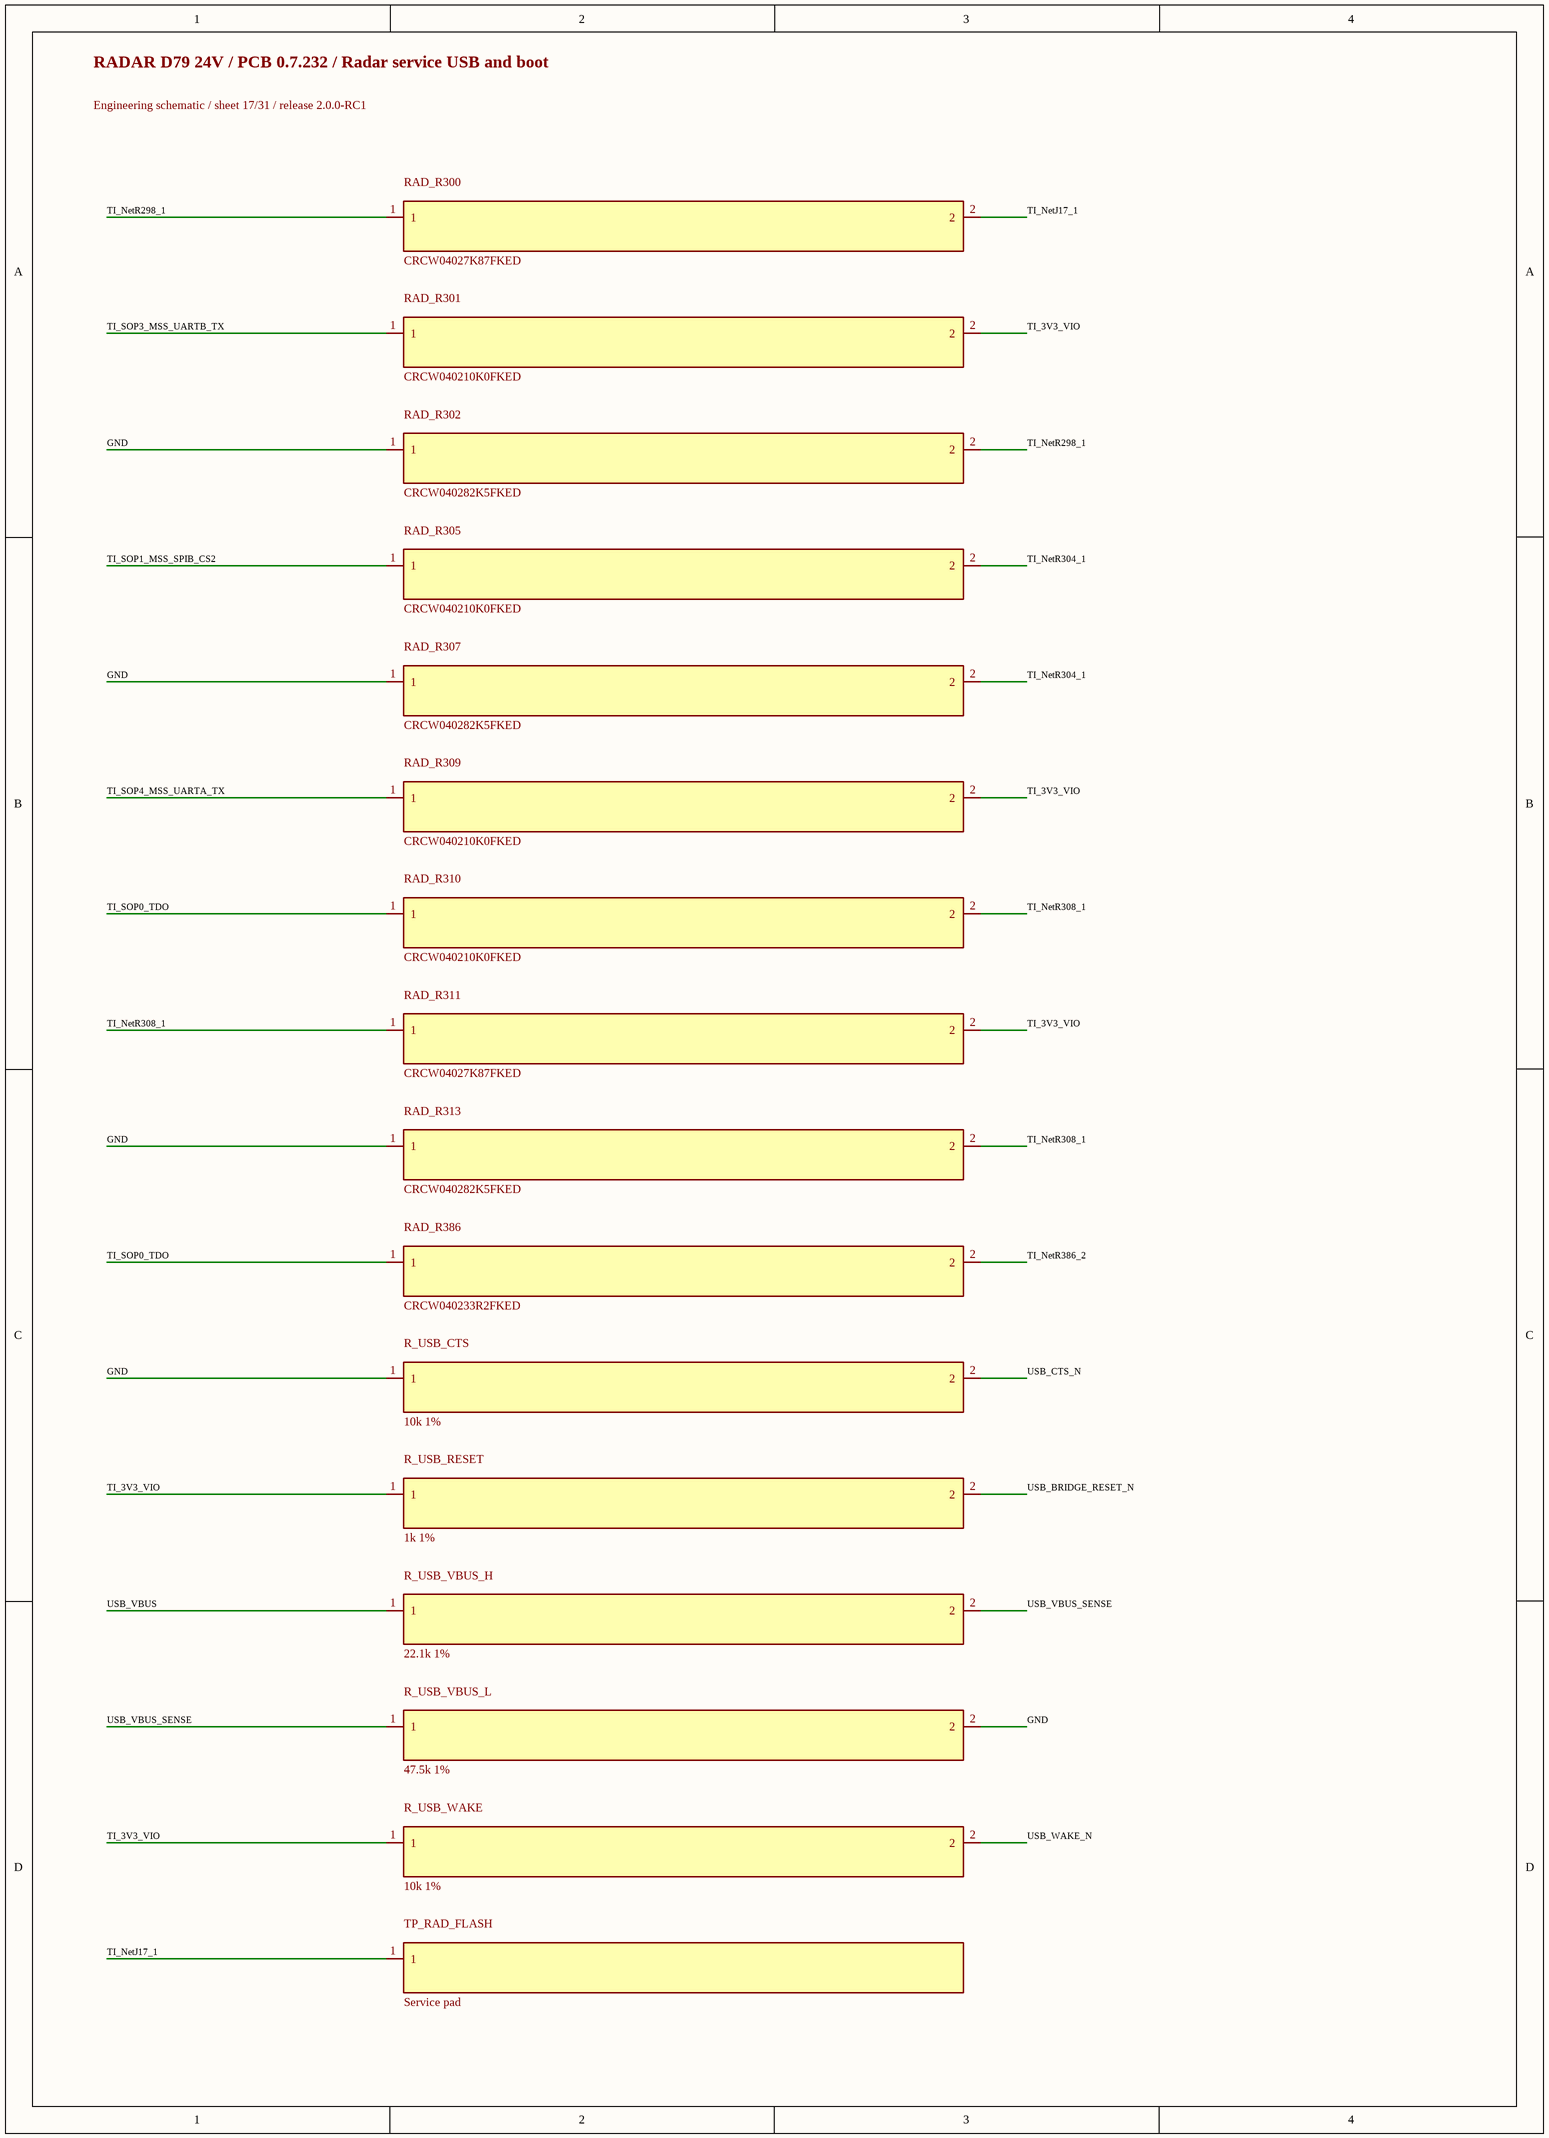
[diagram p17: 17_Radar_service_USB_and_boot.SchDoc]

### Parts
R_USB_CTS  10k 1%  [R_0402_1005Metric]
R_USB_RESET  1k 1%  [R_0402_1005Metric]
R_USB_VBUS_H  22.1k 1%  [R_0402_1005Metric]
R_USB_VBUS_L  47.5k 1%  [R_0402_1005Metric]
R_USB_WAKE  10k 1%  [R_0402_1005Metric]
RAD_R300  CRCW04027K87FKED  [0402L]
RAD_R301  CRCW040210K0FKED  [0402L]
RAD_R302  CRCW040282K5FKED  [0402L]
RAD_R305  CRCW040210K0FKED  [0402L]
RAD_R307  CRCW040282K5FKED  [0402L]
RAD_R309  CRCW040210K0FKED  [0402L]
RAD_R310  CRCW040210K0FKED  [0402L]
RAD_R311  CRCW04027K87FKED  [0402L]
RAD_R313  CRCW040282K5FKED  [0402L]
RAD_R386  CRCW040233R2FKED  [0402L]
TP_RAD_FLASH  Service pad  [TestPoint_Pad_D1.5mm]

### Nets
GND: R_USB_CTS.1 R_USB_VBUS_L.2 RAD_R302.1 RAD_R307.1 RAD_R313.1
TI_3V3_VIO: R_USB_RESET.1 R_USB_WAKE.1 RAD_R301.2 RAD_R309.2 RAD_R311.2
TI_NetJ17_1: RAD_R300.2 TP_RAD_FLASH.1
TI_NetR298_1: RAD_R300.1 RAD_R302.2
TI_NetR304_1: RAD_R305.2 RAD_R307.2
TI_NetR308_1: RAD_R310.2 RAD_R311.1 RAD_R313.2
TI_NetR386_2: RAD_R386.2
TI_SOP0_TDO: RAD_R310.1 RAD_R386.1
TI_SOP1_MSS_SPIB_CS2: RAD_R305.1
TI_SOP3_MSS_UARTB_TX: RAD_R301.1
TI_SOP4_MSS_UARTA_TX: RAD_R309.1
USB_BRIDGE_RESET_N: R_USB_RESET.2
USB_CTS_N: R_USB_CTS.2
USB_VBUS: R_USB_VBUS_H.1
USB_VBUS_SENSE: R_USB_VBUS_H.2 R_USB_VBUS_L.1
USB_WAKE_N: R_USB_WAKE.2

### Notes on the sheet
- RADAR D79 24V / PCB 0.7.232 / Radar service USB and boot
- Engineering schematic / sheet 17/31 / release 2.0.0-RC1

## Sheet 18_Radar_service_USB_and_boot.SchDoc
size 289 x 396 mm
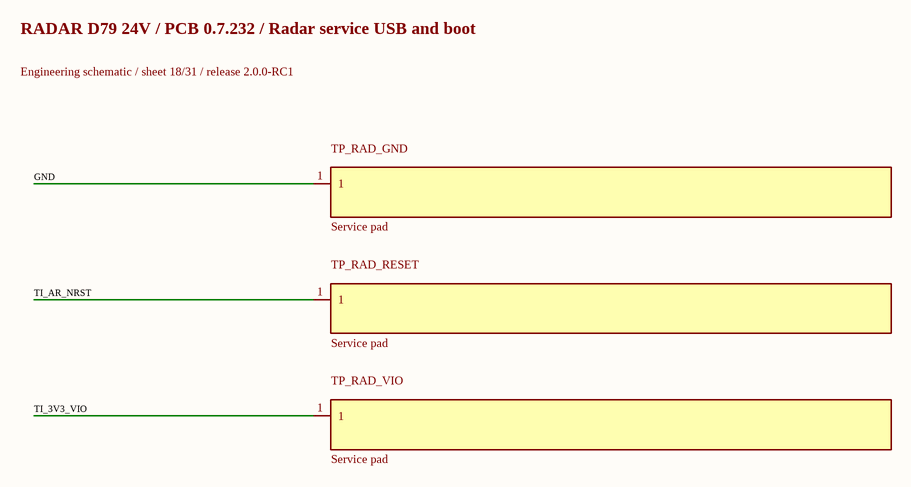
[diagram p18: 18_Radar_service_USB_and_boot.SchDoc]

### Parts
TP_RAD_GND  Service pad  [TestPoint_Pad_D1.5mm]
TP_RAD_RESET  Service pad  [TestPoint_Pad_D1.5mm]
TP_RAD_VIO  Service pad  [TestPoint_Pad_D1.5mm]

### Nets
GND: TP_RAD_GND.1
TI_3V3_VIO: TP_RAD_VIO.1
TI_AR_NRST: TP_RAD_RESET.1

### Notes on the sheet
- RADAR D79 24V / PCB 0.7.232 / Radar service USB and boot
- Engineering schematic / sheet 18/31 / release 2.0.0-RC1

## Sheet 19_Radar_12V_to_3V3.SchDoc
size 289 x 401 mm
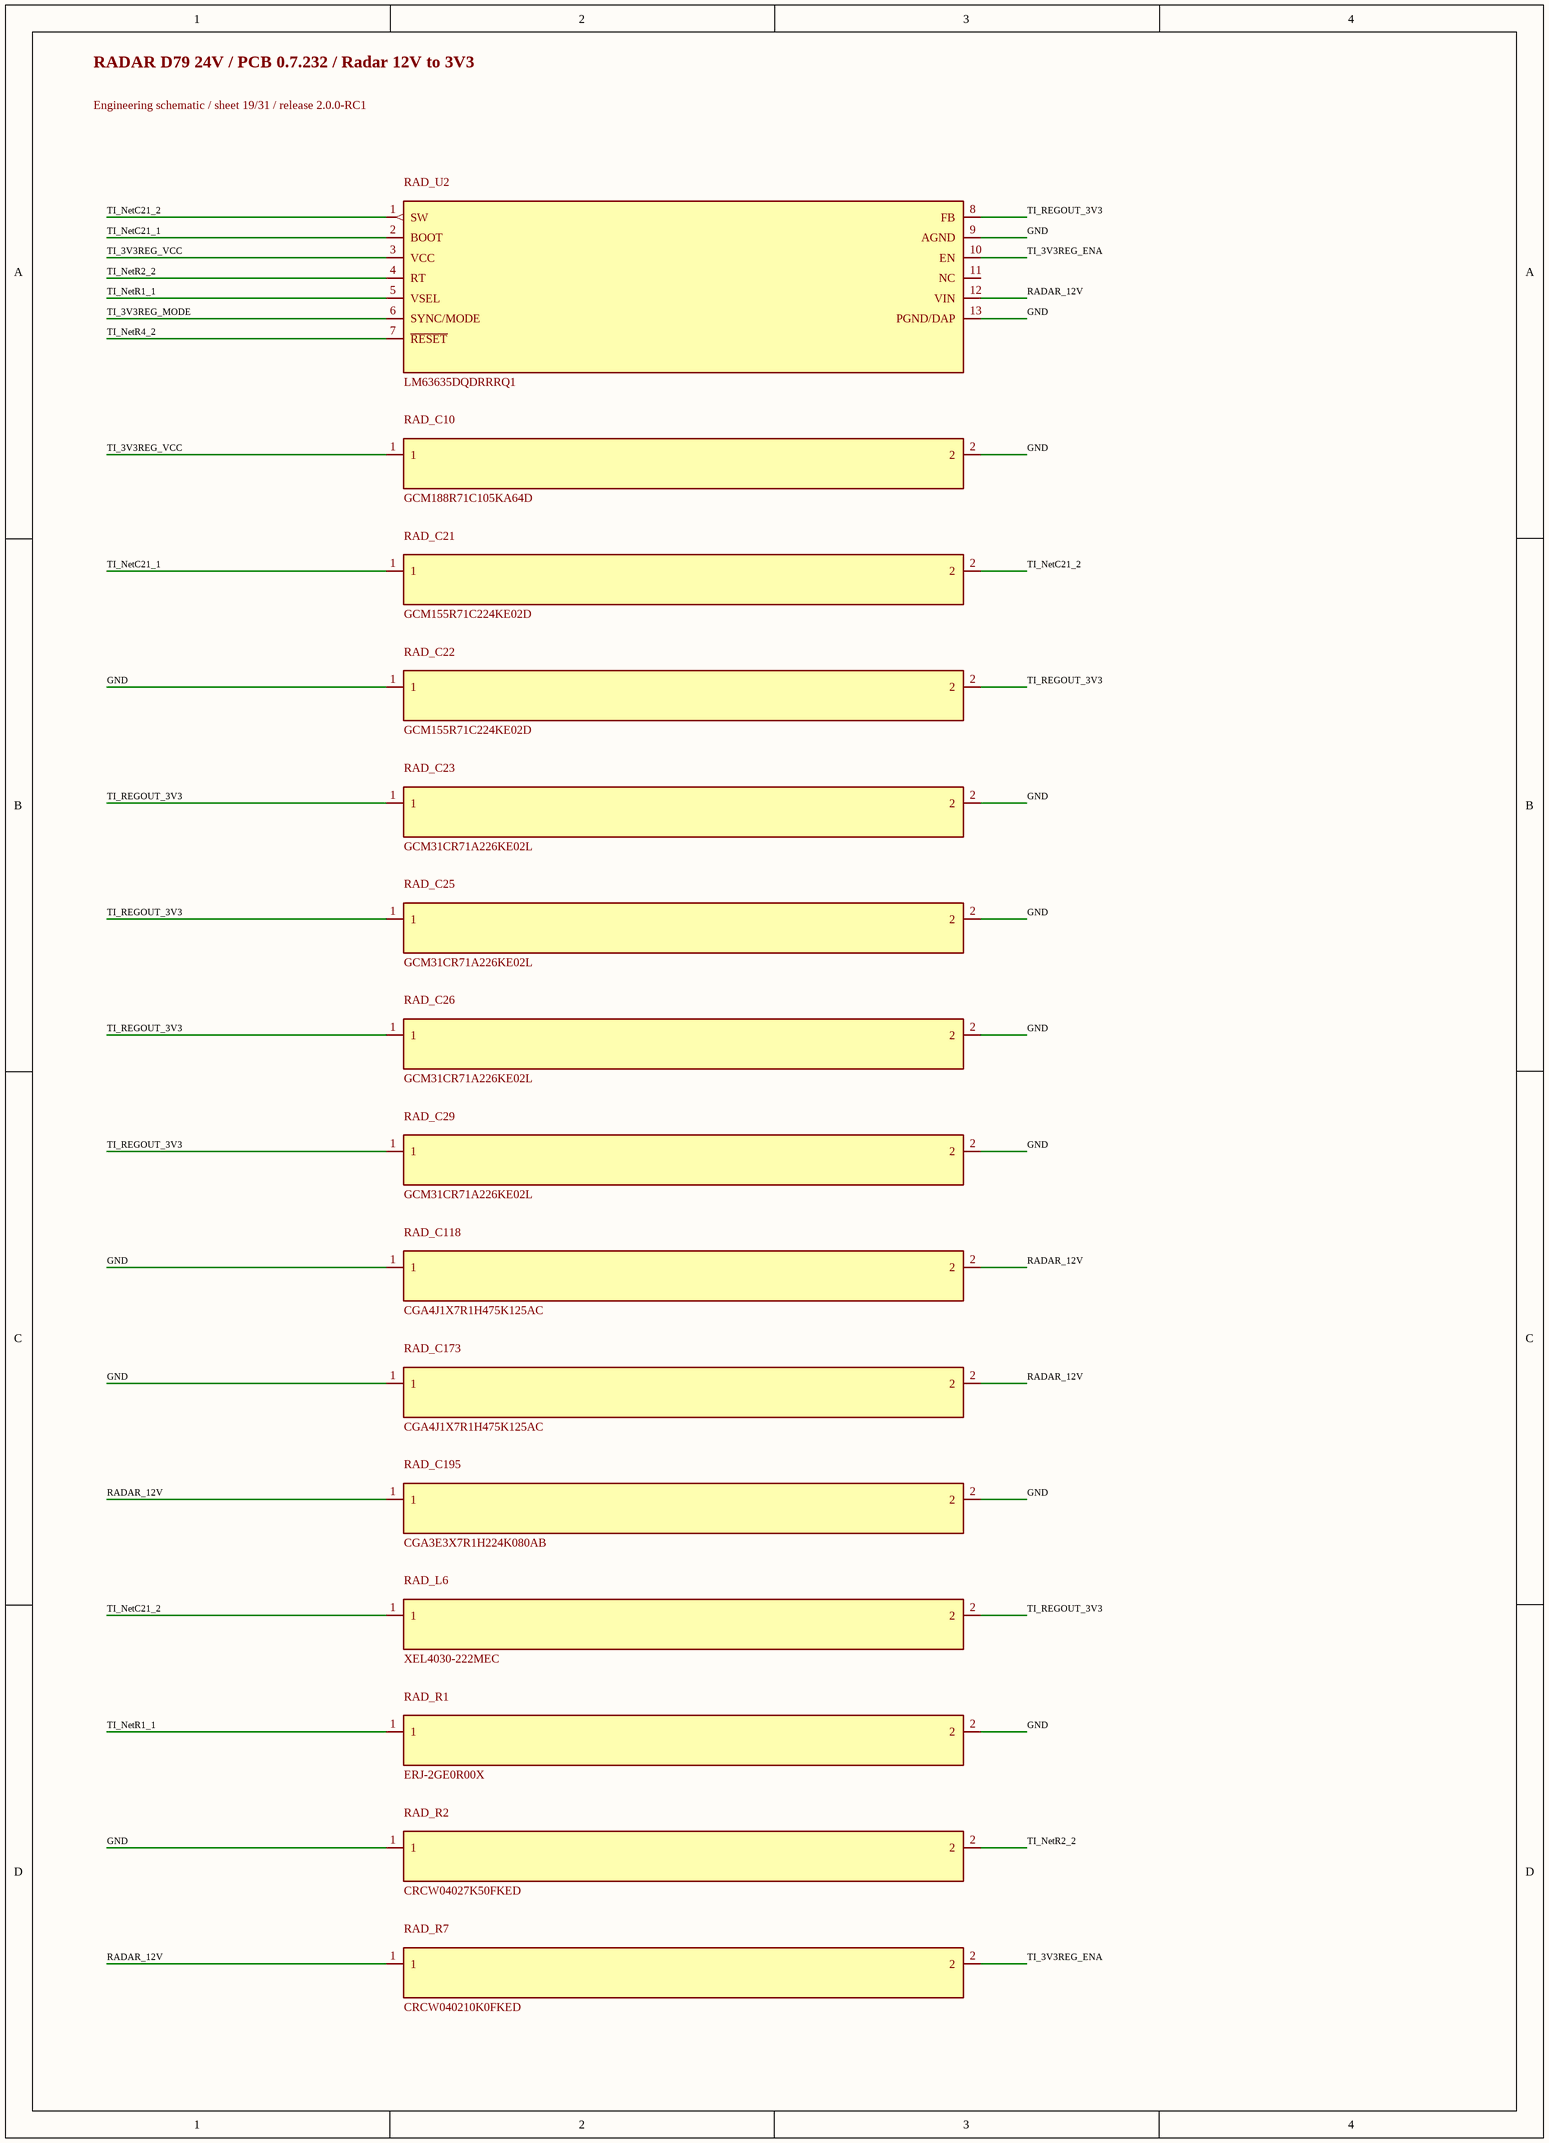
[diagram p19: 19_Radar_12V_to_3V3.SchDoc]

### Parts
RAD_C10  GCM188R71C105KA64D  [0603L]
RAD_C21  GCM155R71C224KE02D  [0402L]
RAD_C22  GCM155R71C224KE02D  [0402L]
RAD_C23  GCM31CR71A226KE02L  [1206_180L]
RAD_C25  GCM31CR71A226KE02L  [1206_180L]
RAD_C26  GCM31CR71A226KE02L  [1206_180L]
RAD_C29  GCM31CR71A226KE02L  [1206_180L]
RAD_C118  CGA4J1X7R1H475K125AC  [FP-CGA4J1X7R1H475K125AC_0805-MFG]
RAD_C173  CGA4J1X7R1H475K125AC  [FP-CGA4J1X7R1H475K125AC_0805-MFG]
RAD_C195  CGA3E3X7R1H224K080AB  [0603L]
RAD_L6  XEL4030-222MEC  [FP-XEL4030-222MEC_SMT2_4MM0_4MM0-MFG]
RAD_R1  ERJ-2GE0R00X  [0402L]
RAD_R2  CRCW04027K50FKED  [0402L]
RAD_R7  CRCW040210K0FKED  [0402L]
RAD_U2  LM63635DQDRRRQ1  [DRR0012E-MFG]

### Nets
GND: RAD_C10.2 RAD_C22.1 RAD_C23.2 RAD_C25.2 RAD_C26.2 RAD_C29.2 RAD_C118.1 RAD_C173.1 RAD_C195.2 RAD_R1.2 RAD_R2.1 RAD_U2.9(AGND) RAD_U2.13(PGND/DAP)
RADAR_12V: RAD_C118.2 RAD_C173.2 RAD_C195.1 RAD_R7.1 RAD_U2.12(VIN)
TI_3V3REG_ENA: RAD_R7.2 RAD_U2.10(EN)
TI_3V3REG_MODE: RAD_U2.6(SYNC/MODE)
TI_3V3REG_VCC: RAD_C10.1 RAD_U2.3(VCC)
TI_NetC21_1: RAD_C21.1 RAD_U2.2(BOOT)
TI_NetC21_2: RAD_C21.2 RAD_L6.1 RAD_U2.1(SW)
TI_NetR1_1: RAD_R1.1 RAD_U2.5(VSEL)
TI_NetR2_2: RAD_R2.2 RAD_U2.4(RT)
TI_NetR4_2: RAD_U2.7(~{RESET})
TI_REGOUT_3V3: RAD_C22.2 RAD_C23.1 RAD_C25.1 RAD_C26.1 RAD_C29.1 RAD_L6.2 RAD_U2.8(FB)

Not connected (* = marked no-connect by the designer): RAD_U2 11(NC)

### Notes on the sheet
- RADAR D79 24V / PCB 0.7.232 / Radar 12V to 3V3
- Engineering schematic / sheet 19/31 / release 2.0.0-RC1

## Sheet 20_Radar_12V_to_3V3.SchDoc
size 289 x 396 mm
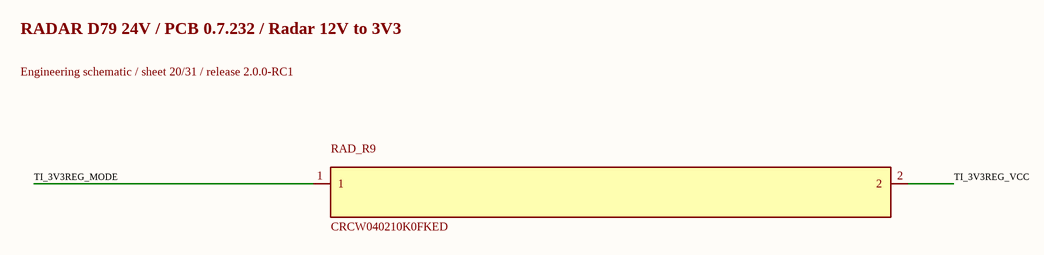
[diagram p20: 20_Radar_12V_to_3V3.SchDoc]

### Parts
RAD_R9  CRCW040210K0FKED  [0402L]

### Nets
TI_3V3REG_MODE: RAD_R9.1
TI_3V3REG_VCC: RAD_R9.2

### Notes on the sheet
- RADAR D79 24V / PCB 0.7.232 / Radar 12V to 3V3
- Engineering schematic / sheet 20/31 / release 2.0.0-RC1

## Sheet 21_Radar_input_and_reference.SchDoc
size 289 x 396 mm
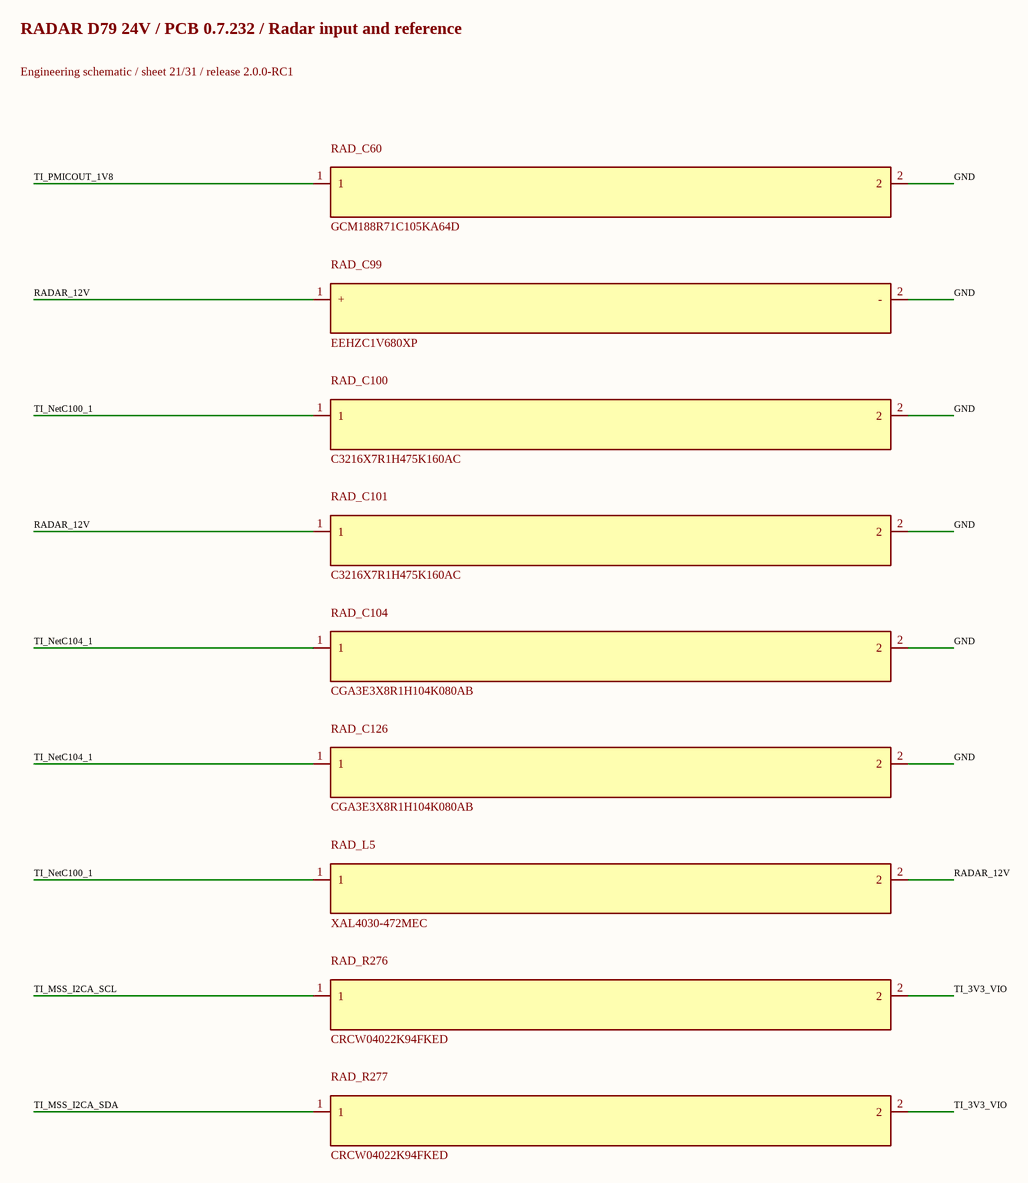
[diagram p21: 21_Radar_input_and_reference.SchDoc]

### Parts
RAD_C60  GCM188R71C105KA64D  [0603L]
RAD_C99  EEHZC1V680XP  [SM_RADIAL_6.3BMM]
RAD_C100  C3216X7R1H475K160AC  [1206_180L]
RAD_C101  C3216X7R1H475K160AC  [1206_180L]
RAD_C104  CGA3E3X8R1H104K080AB  [0603L]
RAD_C126  CGA3E3X8R1H104K080AB  [0603L]
RAD_L5  XAL4030-472MEC  [FP-XAL4030-472MEC_SMD2-MFG]
RAD_R276  CRCW04022K94FKED  [0402L]
RAD_R277  CRCW04022K94FKED  [0402L]

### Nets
GND: RAD_C60.2 RAD_C99.2(-) RAD_C100.2 RAD_C101.2 RAD_C104.2 RAD_C126.2
RADAR_12V: RAD_C99.1(+) RAD_C101.1 RAD_L5.2
TI_3V3_VIO: RAD_R276.2 RAD_R277.2
TI_MSS_I2CA_SCL: RAD_R276.1
TI_MSS_I2CA_SDA: RAD_R277.1
TI_NetC100_1: RAD_C100.1 RAD_L5.1
TI_NetC104_1: RAD_C104.1 RAD_C126.1
TI_PMICOUT_1V8: RAD_C60.1

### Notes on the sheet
- RADAR D79 24V / PCB 0.7.232 / Radar input and reference
- Engineering schematic / sheet 21/31 / release 2.0.0-RC1

## Sheet 22_Radar_bypass.SchDoc
size 289 x 396 mm
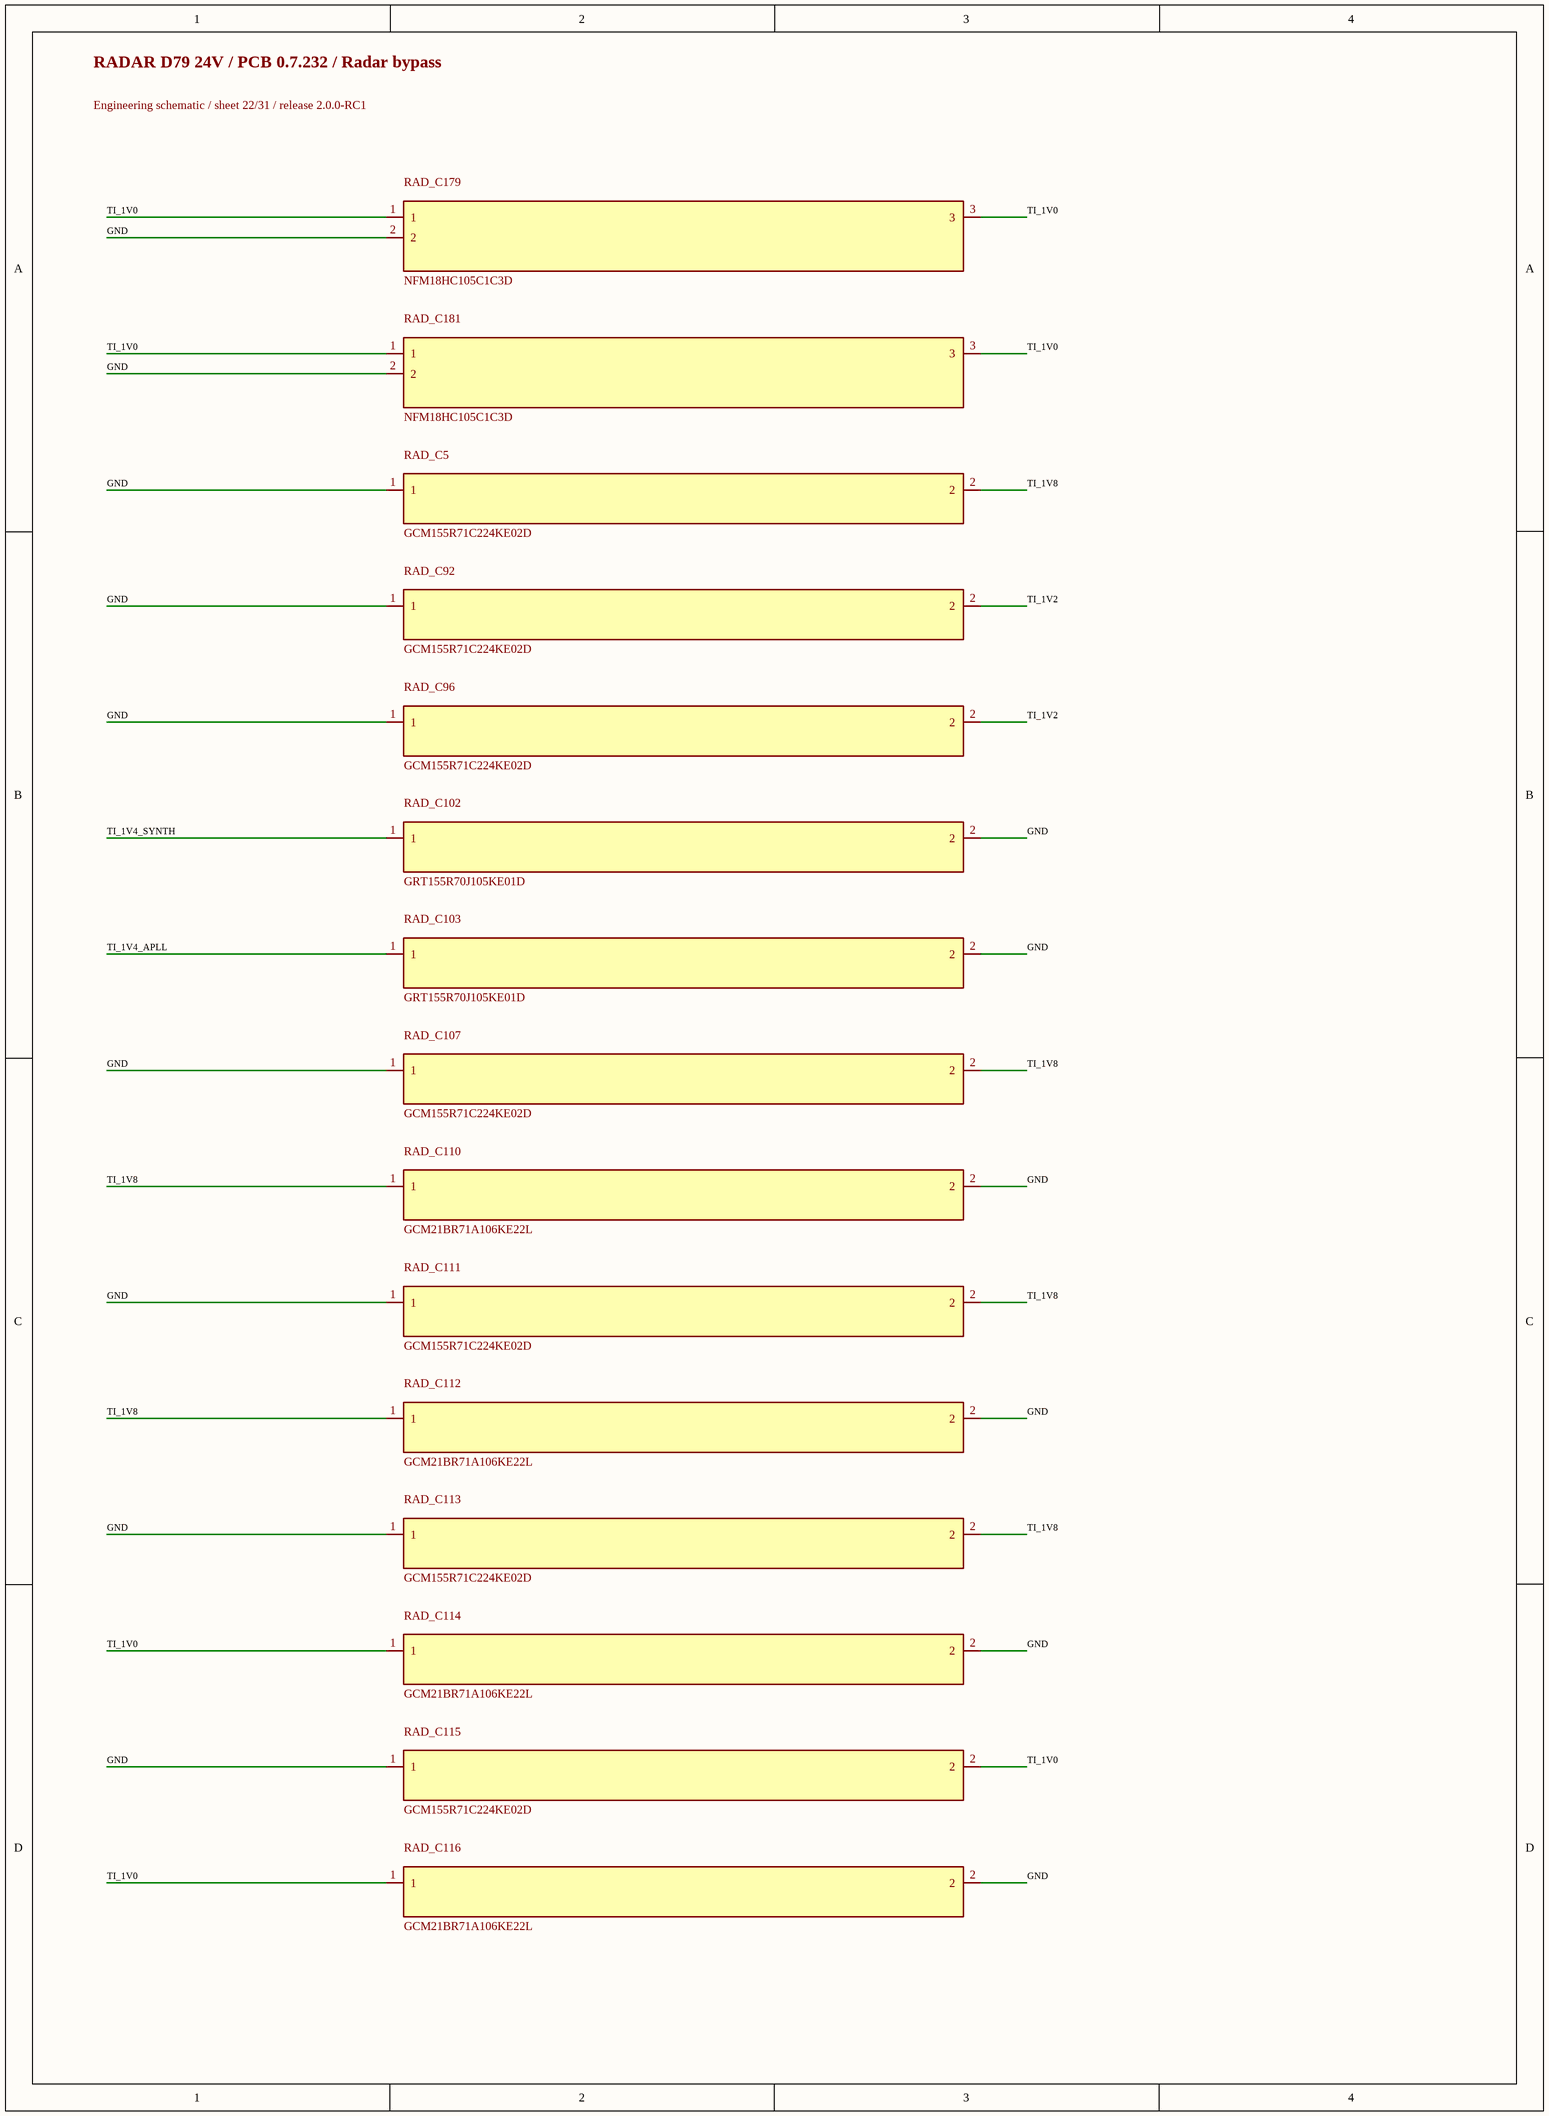
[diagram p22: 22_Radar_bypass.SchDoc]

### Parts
RAD_C5  GCM155R71C224KE02D  [0402L]
RAD_C92  GCM155R71C224KE02D  [0402L]
RAD_C96  GCM155R71C224KE02D  [0402L]
RAD_C102  GRT155R70J105KE01D  [FP-GRT155R70J105KE01D_0402-MFG]
RAD_C103  GRT155R70J105KE01D  [FP-GRT155R70J105KE01D_0402-MFG]
RAD_C107  GCM155R71C224KE02D  [0402L]
RAD_C110  GCM21BR71A106KE22L  [0805L]
RAD_C111  GCM155R71C224KE02D  [0402L]
RAD_C112  GCM21BR71A106KE22L  [0805L]
RAD_C113  GCM155R71C224KE02D  [0402L]
RAD_C114  GCM21BR71A106KE22L  [0805L]
RAD_C115  GCM155R71C224KE02D  [0402L]
RAD_C116  GCM21BR71A106KE22L  [0805L]
RAD_C179  NFM18HC105C1C3D  [FP-NFM18HC105C1C3D_0603-MFG]
RAD_C181  NFM18HC105C1C3D  [FP-NFM18HC105C1C3D_0603-MFG]

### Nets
GND: RAD_C5.1 RAD_C92.1 RAD_C96.1 RAD_C102.2 RAD_C103.2 RAD_C107.1 RAD_C110.2 RAD_C111.1 RAD_C112.2 RAD_C113.1 RAD_C114.2 RAD_C115.1 RAD_C116.2 RAD_C179.2 RAD_C181.2
TI_1V0: RAD_C114.1 RAD_C115.2 RAD_C116.1 RAD_C179.1 RAD_C179.3 RAD_C181.1 RAD_C181.3
TI_1V2: RAD_C92.2 RAD_C96.2
TI_1V4_APLL: RAD_C103.1
TI_1V4_SYNTH: RAD_C102.1
TI_1V8: RAD_C5.2 RAD_C107.2 RAD_C110.1 RAD_C111.2 RAD_C112.1 RAD_C113.2

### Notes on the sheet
- RADAR D79 24V / PCB 0.7.232 / Radar bypass
- Engineering schematic / sheet 22/31 / release 2.0.0-RC1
